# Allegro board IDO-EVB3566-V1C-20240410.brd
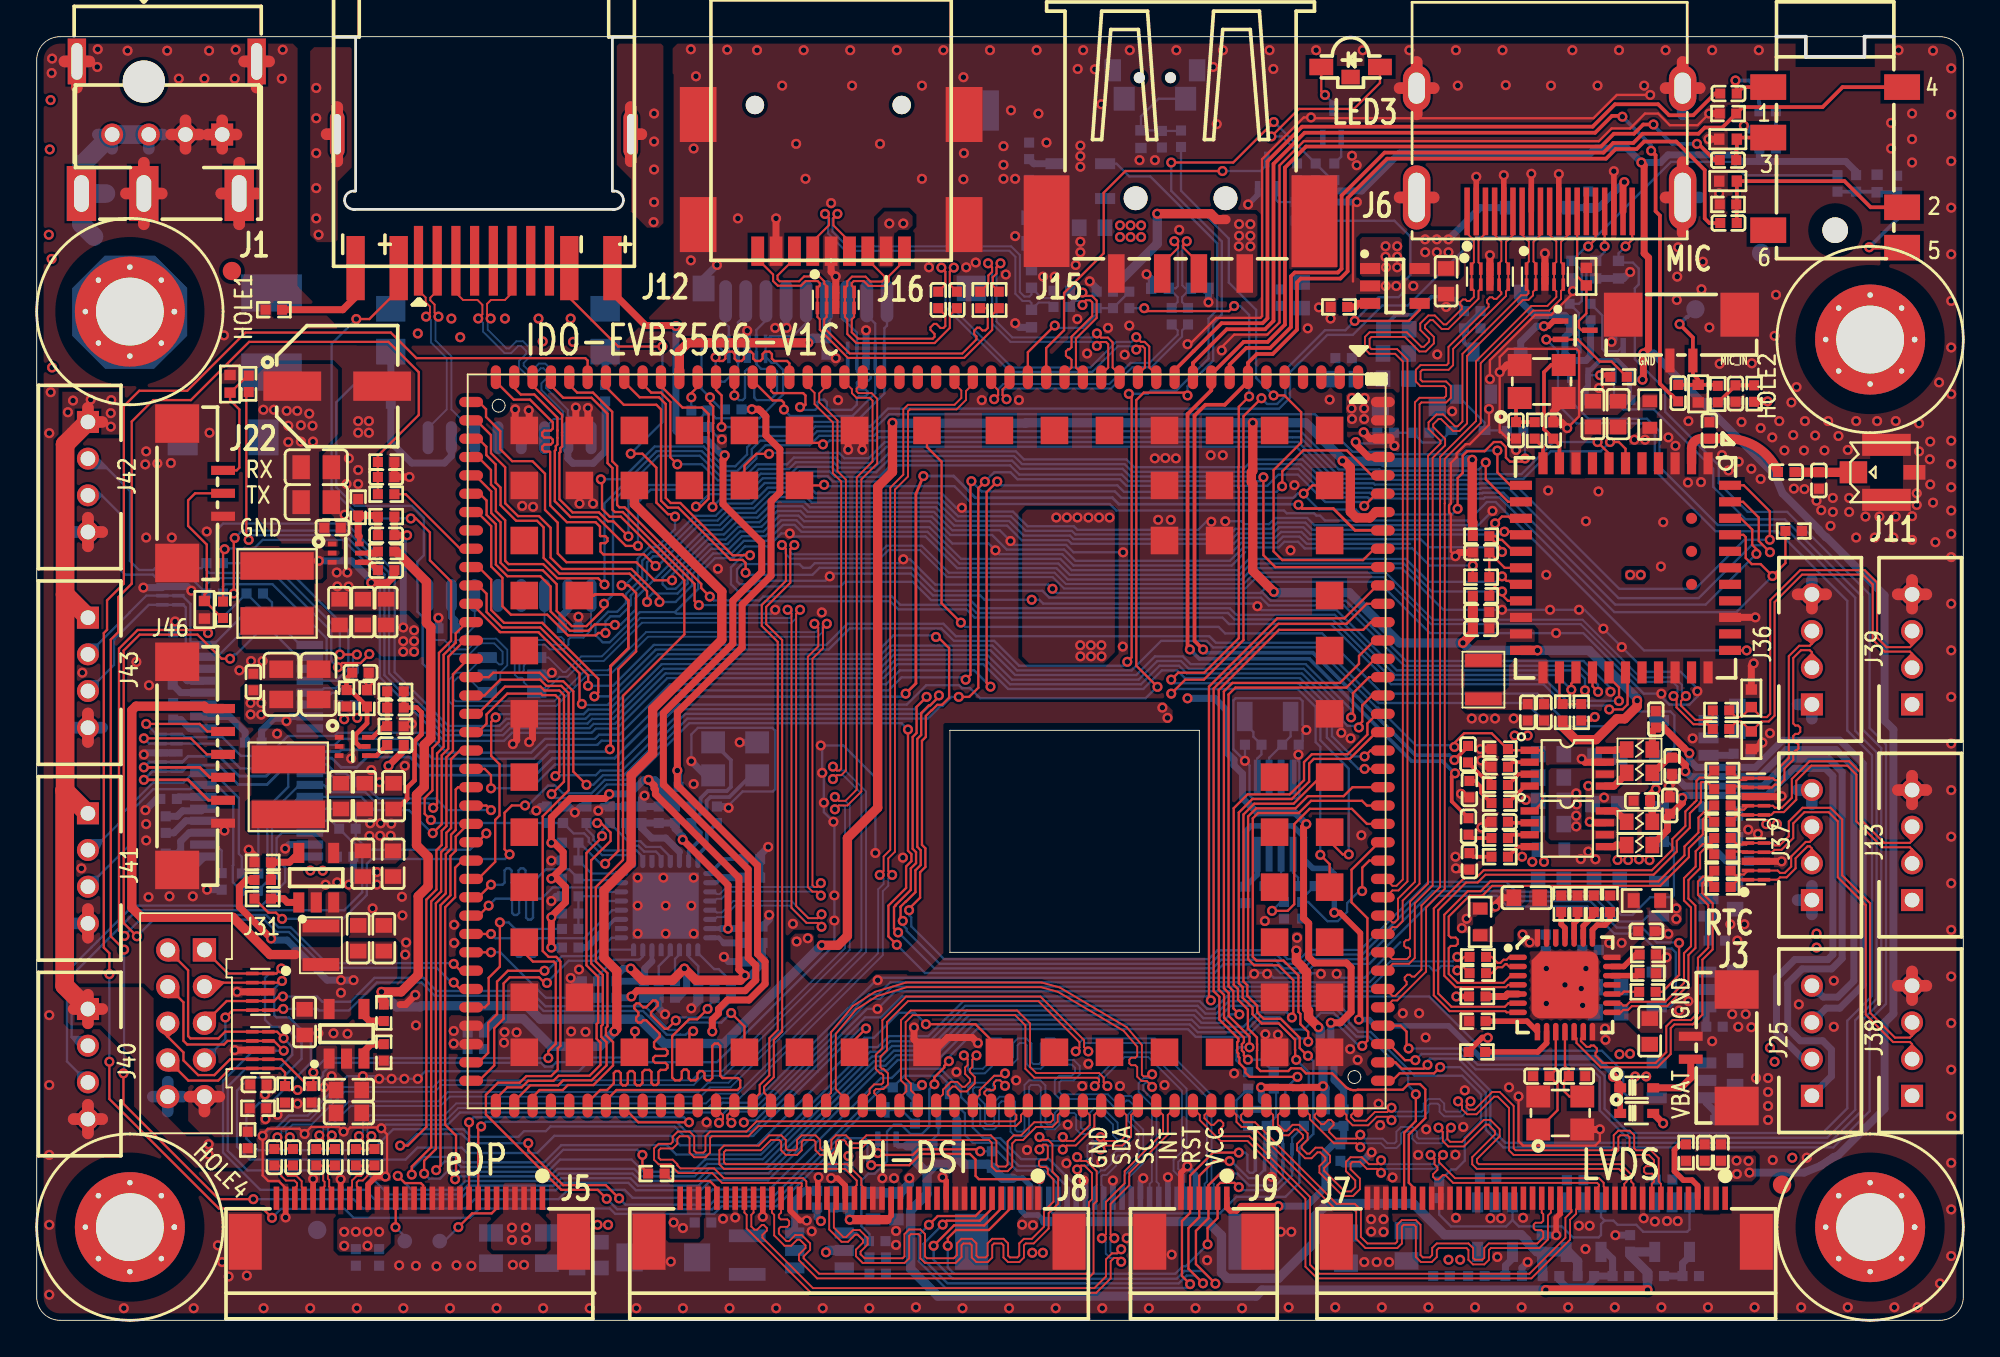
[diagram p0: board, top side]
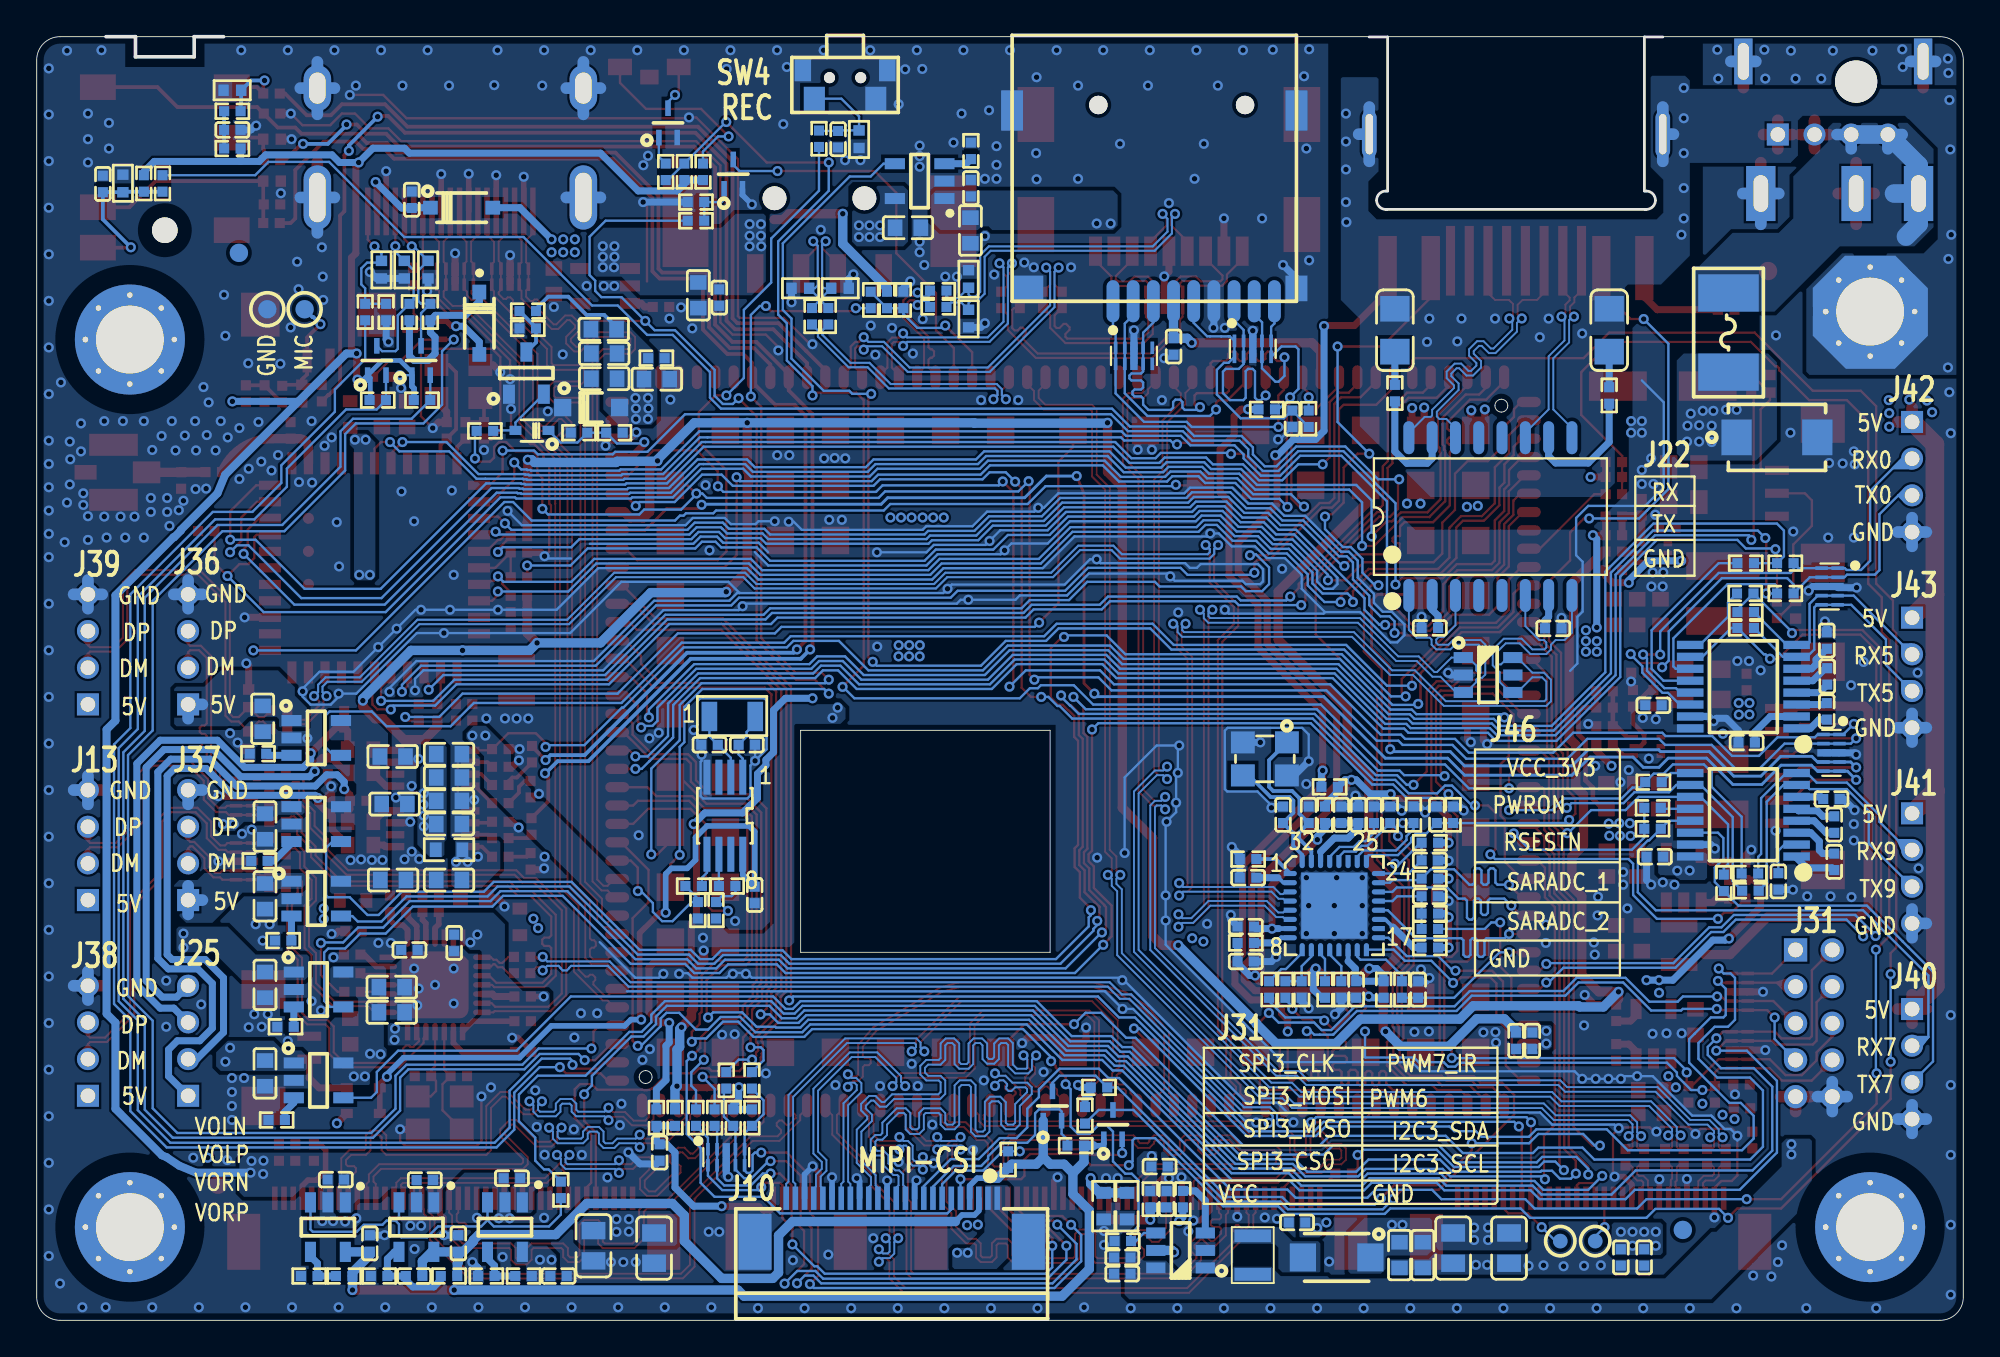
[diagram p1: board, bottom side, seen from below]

Outline 105.03 x 69.98 mm; copper layers: TOP, L2_GND, L3_S2, BOTTOM. Coordinates in mm from the lower left corner of the outline.
Outline path: 0,68.71 0,1.27 arc(0.37,0.37) 1.27,0 103.76,0 arc(104.66,0.37) 105.03,1.27 105.03,68.71 arc(104.66,69.61) 103.76,69.98 1.27,69.98 arc(0.37,69.61) 0,68.71

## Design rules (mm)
net group DIFFPAIR0: nets USB_HOST3_DM USB_HOST3_DP
net group DIFFPAIR1: nets USB_HOST2_DM USB_HOST2_DP
net group DIFFPAIR2: nets MIPI_CSI_RX_CLK0N MIPI_CSI_RX_CLK0P
net group DIFFPAIR3: nets MIPI_CSI_RX_D3N MIPI_CSI_RX_D3P
net group DIFFPAIR4: nets MIPI_CSI_RX_D2N MIPI_CSI_RX_D2P
net group DIFFPAIR5: nets MIPI_CSI_RX_D1N MIPI_CSI_RX_D1P
net group DIFFPAIR6: nets MIPI_CSI_RX_D0N MIPI_CSI_RX_D0P
net group DIFFPAIR7: nets MIPI_DSI_TX1_CLKN MIPI_DSI_TX1_CLKP
net group DIFFPAIR8: nets MIPI_DSI_TX1_D3N MIPI_DSI_TX1_D3P
net group DIFFPAIR9: nets MIPI_DSI_TX1_D2N MIPI_DSI_TX1_D2P
net group DIFFPAIR10: nets MIPI_DSI_TX1_D1N MIPI_DSI_TX1_D1P
net group DIFFPAIR11: nets MIPI_DSI_TX1_D0N MIPI_DSI_TX1_D0P
net group DIFFPAIR12: nets MIPI_DSI_TX0_CLKN/LVDS_TX0_CLKN MIPI_DSI_TX0_CLKP/LVDS_TX0_CLKP
net group DIFFPAIR13: nets MIPI_DSI_TX0_D3N/LVDS_TX0_D3N MIPI_DSI_TX0_D3P/LVDS_TX0_D3P
net group DIFFPAIR14: nets MIPI_DSI_TX0_D2N/LVDS_TX0_D2N MIPI_DSI_TX0_D2P/LVDS_TX0_D2P
net group DIFFPAIR15: nets MIPI_DSI_TX0_D1N/LVDS_TX0_D1N MIPI_DSI_TX0_D1P/LVDS_TX0_D1P
net group DIFFPAIR16: nets MIPI_DSI_TX0_D0N/LVDS_TX0_D0N MIPI_DSI_TX0_D0P/LVDS_TX0_D0P
net group DIFFPAIR17: nets HDMI_TX_CLKN HDMI_TX_CLKP
net group DIFFPAIR18: nets HDMI_TX_D0N HDMI_TX_D0P
net group DIFFPAIR19: nets HDMI_TX_D1N HDMI_TX_D1P
net group DIFFPAIR20: nets HDMI_TX_D2N HDMI_TX_D2P
net group DIFFPAIR21: nets USB3_HOST1SSRXN USB3_HOST1SSRXP
net group DIFFPAIR22: nets USB3_HOST1SSTXN USB3_HOST1SSTXP
net group DIFFPAIR23: nets USB_OTG0_DM_2 USB_OTG0_DP_2
net group DIFFPAIR48: nets RXN RXP
net group 90OHM: nets FE1.1_DM1 FE1.1_DM1_ FE1.1_DM2 FE1.1_DM2_ FE1.1_DM3 FE1.1_DM3_ FE1.1_DM4 FE1.1_DM4_ FE1.1_DP1 FE1.1_DP1_ FE1.1_DP2 FE1.1_DP2_ FE1.1_DP3 FE1.1_DP3_ FE1.1_DP4 FE1.1_DP4_ FE1_1_DM0 FE2_1_DP0 USB3_HOST1_DM USB3_HOST1_DM_2 USB3_HOST1_DP USB3_HOST1_DP_2 USB3_HOST1_SSRXN USB3_HOST1_SSRXP USB3_HOST1_SSTXN USB3_HOST1_SSTXP USB_HOST2_DM_ USB_HOST2_DP_ USB_OTG0_DM USB_OTG0_DP
net group 100OHM: nets EDP_TX_AUXN EDP_TX_AUXN_ EDP_TX_AUXP EDP_TX_AUXP_ EDP_TX_D0N EDP_TX_D0N_ EDP_TX_D0P EDP_TX_D0P_ EDP_TX_D1N EDP_TX_D1N_ EDP_TX_D1P EDP_TX_D1P_ RN RP TN TP TXN TXP

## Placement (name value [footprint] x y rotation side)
C1  100uF/25V  [CAPAE660X540]  16.38 50.93 0 top
C2  100nF  [C0402]  19.56 31.37 180 top
C3  100nF  [C0402]  19.05 40.89 180 top
C4  10uF  [C0805]  13.34 34.67 270 top
C5  10uF  [C0805]  15.37 34.67 270 top
C6  100pF  [C0402]  19.56 33.4 0 top
C7  22uF  [C0603]  17.88 28.57 270 top
C8  22uF  [C0603]  17.78 24.89 90 top
C9  100nF  [C0402]  11.81 34.8 270 top
C10  22uF  [C0603]  19.46 28.57 270 top
C11  10uF  [C0805]  15.24 44.6 180 top
C12  10uF  [C0805]  15.24 46.51 180 top
C13  100pF  [C0402]  19.05 42.8 0 top
C14  22uF  [C0603]  16.51 38.61 270 top
C15  22uF  [C0603]  17.78 38.61 270 top
C16  22uF  [C0603]  19.05 38.61 270 top
C17  100nF  [C0402]  16.13 43.21 180 top
C18  22uF  [C0603]  16.59 28.57 270 top
C20  22uF  [C0603]  19.43 24.89 90 top
C21  22uF  [C0603]  18.92 20.83 270 top
C22  22uF  [C0603]  14.61 16.26 90 top
C23  22uF  [C0603]  17.53 20.83 270 top
C24  22uF  [C0603]  17.02 11.3 180 top
C25  22uF  [C0603]  17.02 12.55 180 top
C26  1uF  [C0402]  23.5 15.24 90 bottom
C27  22uF  [C0603]  74.09 51.33 180 bottom
C28  22uF  [C0603]  71.22 51.31 0 bottom
C29  1uF  [C0402]  24.38 15.24 90 bottom
C30  18pF  [C0402]  66.32 31.38 0 bottom
C31  18pF  [C0402]  68.35 31.38 180 bottom
C32  1uF  [C0402]  65.89 23.19 90 bottom
C33  100nF  [C0402]  61.34 64.39 90 bottom
C34  100nF  [C0402]  18.41 8.89 90 top
C35  100nF  [C0402]  17.4 8.89 90 top
C36  100nF  [C0402]  12.95 8.89 90 top
C37  100nF  [C0402]  13.97 8.89 90 top
C38  100nF  [C0402]  15.24 8.89 90 top
C39  100nF  [C0402]  16.26 8.89 90 top
C40  10uF  [C0402]  17.4 3.43 90 bottom
C41  10uF  [C0402]  18.67 3.43 90 bottom
C42  10uF  [C0805]  27.81 3.94 90 bottom
C43  10uF  [C0805]  24.77 3.94 90 bottom
C47  1uF  [C0402]  84.58 61.09 270 bottom
C48  10uF  [C0402]  90.93 9.14 270 top
C49  10uF  [C0402]  91.82 9.14 270 top
C50  10uF  [C0805]  74.68 4.06 90 bottom
C51  10uF  [C0805]  71.37 3.94 90 bottom
C53  1uF  [C0402]  43.43 6.6 270 bottom
C54  10uF  [C0402]  43.81 8.38 0 bottom
C55  10uF  [C0402]  36.32 5.33 180 bottom
C57  100nF  [C0402]  45.85 2.54 180 bottom
C58  1uF  [C0603]  29.46 3.56 90 bottom
C59  4.7uF  [C0402]  45.85 3.43 180 bottom
C60  1uF  [C0603]  30.73 3.56 90 bottom
C61  1uF  [C0402]  71.07 9.14 270 bottom
C62  NC/6.8pF  [C0402]  19.05 45.97 180 top
C63  10uF  [C0402]  79.12 7.75 180 bottom
C64  10uF  [C0402]  76.58 2.41 0 bottom
C67  10uF  [C0402]  88.72 7.67 180 bottom
C68  10uF  [C0402]  86.87 4.19 270 bottom
C72  10uF  [C0402]  83.87 7.65 180 bottom
C73  10uF  [C0402]  82.04 4.19 270 bottom
C76  NC/6.8pF  [C0402]  78.74 41.86 0 top
C77  10pF  [C0402]  95.38 46.24 180 top
C78  18pF  [C0402]  82.68 48.51 90 top
C79  NC/10pF  [C0402]  91.19 48.51 270 top
C80  NC/10pF  [C0402]  97.16 45.78 90 top
C81  18pF  [C0402]  80.64 48.51 90 top
C82  22uF  [C0603]  84.84 49.4 270 top
C83  22uF  [C0603]  86.21 49.4 270 top
C85  1uF  [C0402]  78.74 37.72 180 top
C86  100nF  [C0402]  78.74 38.61 180 top
C90  4.7uF  [C0402]  81.28 33.15 90 top
C91  100nF  [C0402]  82.17 33.15 90 top
C123  10uF  [C0603]  76.83 56.64 270 top
C124  10uF  [C0603]  57.53 59.56 180 bottom
C125  100nF  [C0402]  50.16 55.63 270 top
C126  100nF  [C0402]  49.15 55.63 270 top
C129  10uF  [C0603]  92.58 18.29 90 bottom
C131  10uF  [C0603]  85.67 18.16 0 bottom
C145  10uF  [C0603]  92.71 32.79 90 bottom
C146  10uF  [C0603]  85.62 30.73 0 bottom
C150  10uF  [C0603]  92.58 23.11 90 bottom
C151  10uF  [C0603]  85.6 24 0 bottom
C153  10uF  [C0603]  92.58 13.46 90 bottom
C154  10uF  [C0603]  85.67 16.79 0 bottom
C155  NC/6.8pF  [C0402]  36.58 49.15 90 bottom
C156  10uF  [C0402]  43.05 53.09 90 bottom
C157  10uF  [C0402]  92.23 59.82 180 top
C158  10uF  [C0402]  92.61 50.52 90 top
C159  NC/100nF  [C0402]  101.42 61.95 270 bottom
C160  10uF  [C0402]  92.2 63.25 180 top
C161  10uF  [C0402]  94.36 64.9 0 bottom
C175  1uF  [C0402]  16.81 25.27 180 bottom
C176  100nF  [C0402]  7.04 24.99 270 bottom
C177  100nF  [C0402]  7.04 27.03 270 bottom
C178  100nF  [C0402]  10.08 23.93 90 bottom
C179  100nF  [C0402]  7.19 28.42 0 bottom
C180  1uF  [C0402]  16.89 33.53 180 bottom
C181  100nF  [C0402]  7.44 33.2 270 bottom
C182  100nF  [C0402]  7.42 35.1 270 bottom
C183  100nF  [C0402]  11.81 31.5 180 bottom
C184  100nF  [C0402]  7.44 37.06 270 bottom
C185  10uF  [C0402]  12.09 12.85 180 top
C186  1uF  [C0402]  79.76 30.18 0 top
C187  100nF  [C0402]  78.03 30.86 270 top
C188  100nF  [C0402]  78.11 28.96 90 top
C192  1nF  [C0402]  88.27 32.77 90 top
C193  1nF  [C0402]  89.15 30.23 270 top
C194  1uF  [C0402]  79.76 27.18 0 top
C195  100nF  [C0402]  78.05 26.92 270 top
C196  100nF  [C0402]  78.11 25.02 90 top
C197  1nF  [C0402]  87.5 28.32 180 top
C198  1nF  [C0402]  89.03 28.07 90 top
C202  18pF  [C0402]  83.97 13.31 180 top
C203  18pF  [C0402]  82.02 13.31 0 top
C298  100nF  [C0402]  87.76 21.21 180 top
C322  100nF  [C0402]  84.71 20.19 0 bottom
C324  100nF  [C0402]  82.27 20.57 90 bottom
C333  22uF  [C0603]  81.23 23.04 0 top
C334  22uF  [C0603]  87.93 15.75 270 top
C341  22uF  [C0603]  68.96 55.88 90 bottom
C343  100nF  [C0402]  67.82 55.75 90 bottom
C344  22uF  [C0603]  54.13 59.41 90 bottom
C346  100nF  [C0402]  54.1 61.72 270 bottom
C357  10uF  [C0603]  85.52 28.14 0 bottom
C358  10uF  [C0603]  92.58 26.92 90 bottom
C359  22uF  [C0603]  82.55 29.59 0 bottom
C360  22uF  [C0603]  82.55 28.32 0 bottom
C361  22uF  [C0603]  82.55 27.05 0 bottom
C362  22uF  [C0603]  82.55 30.86 0 bottom
C363  22uF  [C0603]  82.55 24 180 bottom
C365  100nF  [C0402]  92.23 66.88 180 top
C366  100nF  [C0402]  89.48 50.55 270 top
C369  22uF  [C0603]  74.12 54.03 180 bottom
C370  22uF  [C0603]  74.09 52.7 180 bottom
C371  100nF  [C0402]  22.35 37.72 0 bottom
C372  100nF  [C0402]  29.08 37.74 180 bottom
C380  10uF  [C0402]  39.12 21.46 180 bottom
C381  10uF  [C0402]  33.1 18.03 90 bottom
C383  NC/6.8pF  [C0402]  29.72 18.03 270 bottom
C384  100nF  [C0402]  29.08 23.11 0 bottom
C385  100nF  [C0402]  38.99 24.13 180 bottom
C386  18pF  [C0402]  37.08 27.56 90 bottom
C387  18pF  [C0402]  35.69 27.56 270 bottom
C388  100nF  [C0402]  32.13 27.56 270 bottom
C389  100nF  [C0402]  33.91 27.56 270 bottom
C390  100nF  [C0402]  32.97 27.56 270 bottom
C391  100nF  [C0402]  39.12 19.56 0 bottom
C392  100pF  [C0402]  29.08 25.07 0 bottom
C393  100pF  [C0402]  28.7 27.56 90 bottom
C394  NC/10pF  [C0402]  84.45 2.41 180 bottom
C395  1nF  [C1206]  19.3 53.98 270 bottom
C396  1nF  [C1206]  30.99 53.98 270 bottom
C397  100nF  [C0402]  17.65 35.31 180 top
D1  SMBJ16A  [SMB_DO-214AA]  10.16 48.13 180 bottom
D2  SMF6.0CA  [SOD-123F]  74.8 49.76 0 bottom
D3  LRB520S-30T1G  [SOD523]  87.22 11.28 0 top
D4  LRB520S-30T1G  [SOD523]  87.22 12.67 0 top
D5  PE0402N12G01B  [V0402]  60.2 64.39 270 bottom
D6  SE05NRC14GA  [DFN2510-10L]  79.22 56.9 0 top
D7  SE05NRC14GA  [DFN2510-10L]  82.22 56.9 0 top
D8  PE0402N12G01B  [V0402]  86.23 57.28 270 bottom
D9  PE0402N12G01B  [V0402]  84.48 56.9 90 top
D10  PE0402N12G01B  [V0402]  83.69 57.28 270 bottom
D11  PE0402N12G01B  [V0402]  84.99 57.28 270 bottom
D12  B5819W-G  [SOD123]  80.9 54.36 270 bottom
D13  B5819W-G  [SOD123]  81.86 60.66 180 bottom
D18  SE05NRC14GA  [DFN2510-10L]  67.44 8.89 180 bottom
D23  SM340AF  [SMAF]  34.16 3.43 180 bottom
D26  PE0402N12G01B  [V0402]  63.4 56.26 180 bottom
D27  PE0402N12G01B  [V0402]  61.24 56.26 180 bottom
D28  PE0402N12G01B  [V0402]  54.23 56.77 270 bottom
D29  PE0402N12G01B  [V0402]  54.23 54.61 270 bottom
D30  SE05NRC14GA  [DFN2510-10L]  43.56 55.63 0 top
D31  SE05NRC14GA  [DFN2510-10L]  93.73 28.55 90 top
D32  SE05NRC14GA  [DFN2510-10L]  93.73 25.02 90 top
D33  SE05NRC14GA  [DFN2510-10L]  45.21 52.58 180 bottom
D34  SE05NRC14GA  [DFN2510-10L]  38.73 52.96 180 bottom
D35  PE0402N12G01B  [V0402]  10.54 51.05 270 top
D36  PE0402N12G01B  [V0402]  9.14 38.73 90 top
D37  PE0402N12G01B  [V0402]  92.2 62.1 180 top
D38  PE0402N12G01B  [V0402]  100.33 61.98 90 bottom
D39  PE0402N12G01B  [V0402]  92.2 64.39 180 top
D40  PE0402N12G01B  [V0402]  94.36 67.06 0 bottom
D41  PE0402N12G01B  [V0402]  90.58 50.52 270 top
D43  SE05NRC14GA  [DFN2510-10L]  7.29 40.01 270 bottom
D44  SE05NRC14GA  [DFN2510-10L]  12.19 17.91 270 top
D45  SE05NRC14GA  [DFN2510-10L]  12.19 14.73 270 top
D46  PE0402N12G01B  [V0402]  93.47 31.62 270 top
D47  PE0402N12G01B  [V0402]  93.47 33.91 90 top
D81  SRV05-4  [SOT23-6]  25.91 35.18 180 bottom
D82  SE05NRC14GA  [DFN2510-10L]  7.19 30.94 270 bottom
D86  LRB520S-30T1G  [SOD523]  78.03 48.51 0 bottom
F1  FUSE_16V/2.6A  [SMD1812]  12.8 53.85 270 bottom
HOLE1  -  [MTG370_600_VIA]  5.08 54.99 0 top
HOLE2  -  [MTG370_600_VIA]  99.95 53.47 0 top
HOLE3  -  [MTG370_600_VIA]  99.95 5.08 0 top
HOLE4  -  [MTG370_600_VIA]  5.08 5.08 0 top
J1  DC-044A-2_5  [DC-044A-2_0-DIP]  5.84 71.63 270 top
J2  PH2.0-4A  [PH200-4A]  7.11 64.64 0 top
J3  MX1.25T-S-2A  [MX125T-S-2A]  90.17 14.86 90 top
J5  FPC05-FDW-30P  [FPC05-30P]  20.32 5.08 0 top
J6  -  [HDMI-TYPEA_SMD]  77.98 60.45 0 top
J7  FPC05-FDW-40P  [FPC05-40P]  82.3 5.08 0 top
J8  FPC05-FDW-40P  [FPC05-40P]  44.83 5.08 0 top
J9  FPC05-UD-6P  [FPC05-6P]  63.63 5.08 0 top
J10  FPC05-PUW-24P  [FPC05-24P]  58.42 5.08 180 bottom
J11  IPEX  [IPEX-001E]  100.84 46.23 180 top
J12  HR6042AS-1188N15B-21-1R  [RJ45_SMD_1188N]  24.38 68.96 180 top
J13  PH2.0-4A  [PH200-4A]  102.23 25.91 270 top
J15  USB-4AF-SMD  [USB_4A_SMD]  62.36 56.77 180 top
J16  USB-9AF-SMD  [JLX-USB-G36]  43.31 57.78 180 top
J21  SD  [TF-01A]  46.35 55.75 0 bottom
J22  MX1.25T-S-3A  [MX125T-S-3A]  10.16 45.09 270 top
J25  PH2.0-4A  [PH200-4A]  96.77 15.24 270 top
J31  PHD2.0-2X5A  [PHD200-2X5A]  9.14 20.19 90 top
J34  PJ-316-6A  [PJ-316A-6A]  98.04 69.98 90 top
J36  PH2.0-4A  [PH200-4A]  96.77 36.58 270 top
J37  PH2.0-4A  [PH200-4A]  96.77 25.91 270 top
J38  PH2.0-4A  [PH200-4A]  102.23 15.24 270 top
J39  PH2.0-4A  [PH200-4A]  102.23 36.58 270 top
J40  PH2.0-4A  [PH200-4A]  2.79 13.97 90 top
J41  PH2.0-4A  [PH200-4A]  2.79 24.64 90 top
J42  PH2.0-4A  [PH200-4A]  2.79 45.97 90 top
J43  PH2.0-4A  [PH200-4A]  2.79 35.31 90 top
J45  MX1.25T-S-2A  [MX125T-S-2A]  89.66 52.32 180 top
J46  MX1.25T-S-6A  [MX125T-S-6A]  10.16 30.23 270 top
L1  2.2uH/4.3A  [IND_404020]  13.72 29.08 270 top
L2  2.2uH/4.3A  [IND_404020]  13.11 39.62 270 top
L3  1uH/3A  [IND_252012]  15.49 20.45 270 top
L5  4.7uH/1.25A  [IND_252012]  38.73 3.56 90 bottom
L6  4.7uH/1.25A  [IND_252012]  78.87 34.92 270 top
L21  UPZ1608E101-3R0TF  [L0603]  87.38 31.11 0 top
L22  UPZ1608E101-3R0TF  [L0603]  87.38 29.84 0 top
L23  UPZ1608E101-3R0TF  [L0603]  87.38 27.18 0 top
L24  UPZ1608E101-3R0TF  [L0603]  87.38 25.91 0 top
LED3  Yellow LED  [LED-SMD_3_2X1_5X1_0]  71.63 68.33 180 top
M1  -  [SOM3566-239P]  73.53 51.56 180 top
MARK1  NC/FID10X20  [FID10X20]  10.64 57.2 0 top
MARK2  NC/FID10X20  [FID10X20]  95.15 7.39 0 top
MARK3  NC/FID10X20  [FID10X20]  15.29 4.93 180 bottom
MARK4  NC/FID10X20  [FID10X20]  94.01 58.19 180 bottom
Q1  MMFTN3019E  [SOT523]  83.87 53.98 0 top
Q2  MMFTN3019E  [SOT523]  84.07 52.32 90 bottom
Q3  MMFTN3019E  [SOT523]  86.49 52.32 90 bottom
Q5  MMFTN3019E  [SOT523]  67.06 62.48 90 bottom
Q8  MMFTN3019E  [SOT523]  46.35 10.67 90 bottom
Q9  MMFTN3019E  [SOT523]  49.66 11.68 90 bottom
Q10  MMFTN3019E  [SOT523]  70.61 65.28 90 bottom
R3  100K  [R0402]  19.56 34.29 0 top
R4  107K  [R0402]  19.05 43.81 0 top
R5  100K  [R0402]  16.89 33.91 90 top
R6  10K  [R0402]  19.05 41.91 180 top
R7  47K  [R0402]  18.01 33.91 270 top
R8  20K  [R0402]  19.56 32.38 180 top
R9  20K  [R0402]  17.53 44.32 270 top
R10  45.3K  [R0402]  12.32 24 180 top
R11  10K  [R0402]  12.32 22.99 0 top
R12  10K  [R0402]  12.32 24.97 0 top
R14  10K  [R0402]  18.92 16.76 90 top
R16  100R  [R0402]  19.05 45.03 0 top
R17  120R  [R0402]  19.05 46.79 180 top
R18  100K  [R0402]  73.53 48.39 180 bottom
R19  4.7K  [R0402]  68.71 62.61 90 bottom
R20  47K  [R0402]  75.46 48.39 180 bottom
R21  2.2K  [R0402]  68.99 22.35 270 bottom
R22  2.2K  [R0402]  68 22.35 270 bottom
R23  22R  [R0402]  67.39 23.67 180 bottom
R24  22R  [R0402]  69.22 23.67 0 bottom
R25  100R  [R0402]  62.38 64.41 90 bottom
R28  4.7K  [R0402]  87.12 54.97 90 bottom
R29  20K  [R0402]  86.23 51.44 180 top
R30  100K  [R0402]  85.98 54.97 90 bottom
R31  10K  [R0402]  84.02 50.16 180 bottom
R32  1.8K  [R0402]  83.57 54.97 90 bottom
R33  10K  [R0402]  86.44 50.16 180 bottom
R34  1.8K  [R0402]  84.71 54.97 90 bottom
R38  0R  [R0402]  44.32 6.6 270 bottom
R39  22R  [R0402]  66.04 13.08 270 bottom
R40  2.2K  [R0402]  66.04 11.05 90 bottom
R41  22R  [R0402]  67.44 13.08 270 bottom
R42  2.2K  [R0402]  67.06 11.05 90 bottom
R43  22R  [R0402]  69.09 11.05 270 bottom
R44  22R  [R0402]  68.07 11.05 270 bottom
R46  0R  [R0402]  70.23 11.05 270 bottom
R47  NC/0R  [R0402]  71.25 11.05 270 bottom
R48  100K  [R0402]  42.55 6.6 90 bottom
R49  100K  [R0402]  45.82 4.32 180 bottom
R50  3.9R  [R0603]  46.86 6.22 90 bottom
R51  3.9R  [R0603]  45.59 6.22 90 bottom
R56  49.9K  [R0402]  78.49 2.41 180 bottom
R57  20K  [R0402]  80.52 2.41 180 bottom
R59  24.9K  [R0402]  88.27 2.41 180 bottom
R60  20K  [R0402]  90.17 2.41 180 bottom
R63  17.4K  [R0402]  82.55 2.41 180 bottom
R64  20K  [R0402]  86.36 2.41 180 bottom
R65  NC/10K  [R0402]  78.74 39.5 0 top
R66  NC/10K  [R0402]  78.74 42.75 0 top
R67  22R  [R0402]  78.74 40.51 0 top
R68  0R  [R0402]  81.66 48.51 270 top
R69  NC/10K  [R0402]  95.78 43.03 0 top
R71  0R  [R0603]  87.93 49.38 90 top
R73  10K  [R0402]  83.19 33.15 90 top
R74  0R  [R0402]  84.2 33.15 90 top
R116  2.2R  [R0402]  62.76 54.74 90 bottom
R117  1K  [R0402]  69.09 59.94 0 bottom
R118  2.2R  [R0402]  61.87 54.74 90 bottom
R119  10K  [R0402]  69.09 60.96 0 bottom
R120  0R  [R0402]  59.56 55.63 90 bottom
R121  10K  [R0402]  58.67 55.63 90 bottom
R122  4.7K  [R0402]  70.99 55.24 0 top
R123  20K  [R0402]  57.78 55.63 270 bottom
R124  2.2R  [R0402]  55.88 56.13 180 bottom
R126  2.2R  [R0402]  55.88 55.24 180 bottom
R127  0R  [R0402]  52.45 55.63 270 top
R128  0R  [R0402]  51.44 55.63 270 top
R129  4.7K  [R0402]  54.1 63.75 270 bottom
R131  2.2R  [R0402]  91.9 27.18 0 top
R132  2.2R  [R0402]  91.9 28.07 0 top
R136  4.7K  [R0402]  91.47 16 0 bottom
R146  2.2R  [R0402]  91.9 28.96 0 top
R148  4.7K  [R0402]  92.96 30.89 0 bottom
R149  2.2R  [R0402]  91.9 29.97 0 top
R151  2.2R  [R0402]  91.9 23.62 0 top
R153  4.7K  [R0402]  91.59 20.7 0 bottom
R154  2.2R  [R0402]  91.9 24.51 0 top
R156  2.2R  [R0402]  91.9 25.4 0 top
R158  4.7K  [R0402]  91.95 10.92 0 bottom
R159  2.2R  [R0402]  91.9 26.29 0 top
R160  22R  [R0402]  35.69 49.15 270 bottom
R161  100R  [R0402]  11.56 51.05 90 top
R162  100R  [R0402]  10.16 38.73 270 top
R163  1K  [R0402]  93.62 50.52 90 top
R164  100K  [R0402]  99.19 61.98 90 bottom
R165  0R  [R0402]  92.2 65.79 0 top
R166  1K  [R0402]  98.17 61.98 270 bottom
R167  1K  [R0402]  91.64 50.5 270 top
R169  1K  [R0402]  94.36 65.91 0 bottom
R170  1K  [R0402]  94.36 63.88 180 bottom
R173  NC/22R  [R0402]  13.06 23.85 270 bottom
R174  NC/22R  [R0402]  16.94 26.8 180 bottom
R175  NC/22R  [R0402]  11.61 23.42 180 bottom
R176  NC/22R  [R0402]  11.63 24.36 180 bottom
R177  22R  [R0402]  16.89 29.34 180 bottom
R178  22R  [R0402]  16.94 27.94 180 bottom
R183  22R  [R0402]  9.7 39.62 180 bottom
R184  22R  [R0402]  9.7 41.27 180 bottom
R185  22R  [R0402]  11.86 37.74 180 bottom
R186  22R  [R0402]  11.86 38.61 180 bottom
R189  NC/22R  [R0402]  11.86 41.27 0 bottom
R190  NC/22R  [R0402]  11.89 39.62 0 bottom
R193  2.2K  [R0402]  14.99 12.32 270 top
R194  2.2K  [R0402]  13.54 12.32 270 top
R195  NC/0R  [R0402]  11.51 9.83 90 top
R196  0R  [R0402]  12.06 11.56 180 top
R197  20K  [R0402]  79.76 29.18 0 top
R198  20K  [R0402]  79.76 28.19 0 top
R199  100K  [R0402]  79.76 31.14 0 top
R200  20K  [R0402]  79.76 26.29 0 top
R201  20K  [R0402]  79.76 25.27 0 top
R231  2.2K  [R0402]  78.26 54.08 180 bottom
R232  1K  [R0402]  78.26 55.02 180 bottom
R292  10K  [R0402]  87.83 18.92 0 top
R293  NC/100K  [R0402]  84.89 22.71 90 top
R294  NC/100K  [R0402]  85.78 22.71 90 top
R295  NC/680R  [R0402]  78.54 16.31 0 top
R296  NC/0R  [R0402]  78.54 17.65 0 top
R297  NC/0R  [R0402]  78.51 14.63 0 top
R298  0R  [R0402]  78.56 18.92 0 top
R299  0R  [R0402]  78.56 19.81 0 top
R300  10K  [R0402]  84 22.71 90 top
R301  10K  [R0402]  83.11 22.71 90 top
R302  10K  [R0402]  87.83 19.94 0 top
R325  2.2R  [R0402]  91.82 32.23 0 top
R326  2.2R  [R0402]  91.82 33.25 0 top
R327  4.7K  [R0402]  92.89 25.04 0 bottom
R331  10K  [R0402]  92.2 60.83 180 top
R333  1.8K  [R0402]  47.12 12.7 180 bottom
R334  1.8K  [R0402]  47.88 11.18 270 bottom
R338  0R  [R0603]  82.55 25.65 0 bottom
R342  22R  [R0402]  33.78 8 0 top
R343  22R  [R0402]  87.81 17.91 0 top
R344  10K  [R0402]  37.97 49.66 180 bottom
R345  0R  [R0603]  87.78 22.89 180 top
R346  0R  [R0603]  78.69 21.72 270 top
R415  10K  [R0402]  69.72 62.61 90 bottom
R500  10K  [R0402]  71.25 52.45 180 bottom
R1201  22R  [R0402]  29.08 21.34 0 bottom
R1202  NC/4.7K  [R0402]  29.08 22.17 180 bottom
R1203  10K  [R0402]  29.08 20.32 180 bottom
R1204  4.7K  [R0402]  29.08 24.08 0 bottom
R1205  22R  [R0402]  36.96 18.03 270 bottom
R1206  22R  [R0402]  37.85 18.03 270 bottom
R1207  2.49K  [R0402]  38.99 25.15 0 bottom
R1209  4.7K  [R0402]  29.97 27.56 270 bottom
R1210  510R  [R0402]  12.93 55.09 0 top
R1211  510R  [R0402]  31.6 18.03 270 bottom
R1212  4.7K  [R0402]  31.24 27.56 90 bottom
R1213  4.7K  [R0402]  39.12 20.57 0 bottom
R1214  4.7K  [R0402]  33.91 18.03 270 bottom
R1215  4.7K  [R0402]  36.07 18.03 270 bottom
R1217  4.7K  [R0402]  27.81 27.56 270 bottom
R1218  4.7K  [R0402]  29.08 26.04 0 bottom
R1219  4.7K  [R0402]  34.8 18.03 270 bottom
R1220  4.7K  [R0402]  18.92 14.61 90 top
R1221  22R  [R0402]  76.45 7.11 270 bottom
R1222  2.2K  [R0402]  52.07 8.76 270 bottom
R1223  2.2K  [R0402]  48.39 9.53 180 bottom
R1224  22R  [R0402]  30.61 18.03 90 bottom
R1225  0R  [R0402]  34.8 27.56 270 bottom
R1226  0R  [R0402]  34.54 29.08 180 bottom
R1227  4.7K  [R0402]  70.74 62.61 90 bottom
R1228  75R  [R0402]  30.99 50.55 90 bottom
R1229  75R  [R0402]  19.3 50.42 90 bottom
R1230  0R  [R0402]  89.92 9.14 90 top
R1231  0R  [R0402]  80.59 48.49 0 bottom
SW4  T-switch  [PB-SIDE-S-3_5X4_5]  60.96 67.94 0 bottom
TP1  -  [TP80]  20.07 4.32 180 bottom
TP2  -  [TP80]  21.97 4.32 180 bottom
TP3  -  [TP100]  90.42 55.12 180 bottom
TP4  -  [TP100]  92.46 55.12 180 bottom
U1  ETA1654FSG  [SOT563]  16.13 32.38 0 top
U2  ETA1654FSG  [SOT563]  15.75 42.93 0 top
U3  ETA3417S2F  [SOT23-5]  15.24 24.13 90 top
U4  ETA6280S2F  [SOT23-5]  16.89 15.62 90 top
U5  HYM8563S  [TSSOP-8]  67.51 27.51 270 bottom
U6  SY7201ABC  [SOT23-6]  42.67 3.81 0 bottom
U7  ETA5050V0S2F  [SOT23-5]  79.5 5.08 270 bottom
U8  ETA5050V0S2F  [SOT23-5]  89.15 5.08 270 bottom
U9  ETA5050V0S2F  [SOT23-5]  84.33 5.08 270 bottom
U10  AP6256  MODULE  [WIFI_44P_12X12]  86.61 41.02 270 top
U11  YT8512C  [QFN-32_5X5X05P]  34.29 22.61 180 bottom
U13  ETA6280S2F  [SOT23-5]  74.04 56.39 0 top
U14  ETA6280S2F  [SOT23-5]  56.9 62.1 0 bottom
U15  ETA6280S2F  [SOT23-5]  89.66 18.03 180 bottom
U17  ETA6280S2F  [SOT23-5]  89.79 31.75 180 bottom
U18  ETA6280S2F  [SOT23-5]  89.79 22.99 180 bottom
U19  ETA6280S2F  [SOT23-5]  89.66 13.08 180 bottom
U21  SP3232EEY-L/TR  [TSSOP-16]  11.99 27.56 0 bottom
U22  NC/SP3232EEY-L/TR  [TSSOP-16]  11.99 34.54 0 bottom
U23  H81621S  [SOP16-P127-710X1270]  25.78 43.81 90 bottom
U24  NS4150B  [MSOP-8]  83.44 30.1 0 top
U25  NS4150B  [MSOP-8]  83.44 26.8 0 top
U26  CH334H  [QFN-28_5X5X05P]  83.31 18.29 0 top
U27  ETA6280S2F  [SOT23-5]  89.79 27.05 180 bottom
U28  NC/SGM803-SXN3L/TR  [SOT23]  78.33 51.64 90 bottom
XT1  32.768KHz  [XTAL_32X15_2P]  67.11 32.92 180 bottom
XT2  37.4MHz  [XTAL_32X25_4P]  82.04 51.18 90 top
XT4  25MHz  [XTAL_32X25_4P]  38.07 30.61 270 bottom
XT5  12MHz  [XTAL_32X25_4P]  83.06 11.3 90 top

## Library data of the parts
C1 = C-G-SMD
C2 C3 C6 C9 C13 C17 C26 C29-C41 C47-C49 C53-C55 C57 C59 C61-C64 C67 C68 C72 C73 C76-C81 C85 C86 C90 C91 C125 C126 C155-C161 C175-C188 C192-C198 C202 C203 C298 C322 C324 C343 C346 C365 C366 C371 C372 C380 C381 C383-C394 C397 = C-0402
C4 C5 C11 C12 C42 C43 C50 C51 = C-0805
C7 C8 C10 C14-C16 C18 C20-C25 C27 C28 C58 C60 C82 C83 C123 C124 C129 C131 C145 C146 C150 C151 C153 C154 C333 C334 C341 C344 C357-C363 C369 C370 = C-0603
C395 C396 = C-1206
D1 D3 D4 D12 D13 D23 D86 = DI-XI-S
D2 = DI-TVS-D
D5 D8-D11 D26-D29 D35-D41 D46 D47 = DI-ESD
D6 D7 D18 D30-D34 D43-D45 D82 = DI-ESD-SE05NRC14GA
D81 = DI-TVS-SRV05-4
F1 = FUSE-SMD1812: User Part Number: HAMP; Tolerance: #TOL
HOLE1-HOLE4 = MH-NOE: Tolerance: RichardLC; User Part Number: pn
J1 = J-DC-044A-2_5
J2 = J-H-4P
J3 J45 = J-A-2P
J5 = J-FPC-30P
J6 = J-HDMI-19P
J7 J8 = J-FPC-40P
J9 = J-FPC-6P
J10 = J-FPC-24P
J11 = RF-IPEX-20279
J12 = J-RJ45-MJ88B-B011-RVL11-P_2
J13 J36-J43 = J-H-4P_0
J15 = J-USB-4AF_1
J16 = J-USB-9AF-W_0
J21 = J-TF-01A
J22 = J-A-3P
J25 = J-H-4P_9
J31 = J-H-2X5P
J34 = J-PJ-316A-6A_0
J46 = J-A-6P
L1-L3 L5 L6 = L-IND
L21-L24 = FB-0603
LED3 = D-LED-CT
M1 = SOM3566-239P_3
MARK1-MARK4 = MARK-FID10X20_0
Q1-Q3 Q5 Q8-Q10 = N-MOS-Q
R3-R12 R14 R16-R25 R28-R34 R38-R44 R46-R49 R56 R57 R59 R60 R63-R69 R73 R74 R116-R124 R126-R129 R131 R132 R136 R146 R148 R149 R151 R153 R154 R156 R158-R167 R169 R170 R173-R178 R183-R186 R189 R190 R193-R201 R231 R232 R292-R302 R325-R327 R331 R333 R334 R342-R344 R415 R500 R1201-R1207 R1209-R1215 R1217-R1231 = R-0402
R50 R51 R71 R338 R345 R346 = R-0603
SW4 = SW-TS24CA
TP1-TP4 = TP-TEST: User Part Number: pn; Tolerance: RichardLC
U1 U2 = U-ETA1654FSG_0
U3 = U-ETA3417S2F
U4 U13-U15 U17-U19 U27 = U-SY6280AAC
U5 = U-HYM8563S
U6 = U-SY7201A_2
U7-U9 = U-ETA5050
U10 = MODULE_AP6XXX
U11 = U-RTL8201F-VB-CG
U21 U22 = U-SP3232EEN
U23 = U-100M-TRANSFORMER
U24 U25 = U-NS4150B
U26 = U-GL850G-60_2
U28 = U-SGM803-SXN3L-TR
XT1 = XTAL-2P
XT2 XT4 XT5 = XTAL-4P

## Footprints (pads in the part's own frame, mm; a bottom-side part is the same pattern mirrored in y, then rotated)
C0402
  rect 0.55x0.55 smd: 1(-0.45,0) 2(0.45,0)
C0603
  rect 0.8x0.9 smd: 1(-0.7,0) 2(0.7,0)
C0805
  rect 0.95x1.3 smd: 1(-0.825,0) 2(0.825,0)
C1206
  rect 1.4x1.6 smd: 1(-1.168,0) 2(1.168,0)
CAPAE660X540
  rect 3.15x1.6 smd: 1(-2.45,0) 2(2.45,0)
DC-044A-2_0-DIP
  round 2.3 hole 2.3 unplated: (4.1,0)
  rect 3x1.6 hole 2x0.8: 2(10.201,5.199) 3(10.201,0) 4(10.201,-3.401)
  rect 2.5x1 hole 2x0.6: 5(3,6.149) 6(3,-3.65)
DFN2510-10L
  rect 0.2x0.68 smd: 1(-1,-0.437) 2(-0.5,-0.437) 4(0.5,-0.437) 5(1,-0.437) 6(1,0.437) 7(0.5,0.437) 9(-0.5,0.437) 10(-1,0.437)
  rect 0.4x0.75 smd: 3(0,-0.395) 8(0,0.395)
FID10X20
  round 1.001 smd: 1(0,0)
FPC05-6P
  rect 0.305x1.27 smd: 1(1.25,1.575) 2(0.75,1.575) 3(0.25,1.575) 4(-0.25,1.575) 5(-0.75,1.575) 6(-1.25,1.575)
  rect 1.803x3.048 smd: 7(2.95,-0.8) 8(-2.95,-0.8)
FPC05-24P
  rect 0.305x1.27 smd: 1(5.75,1.575) 2(5.25,1.575) 3(4.75,1.575) 4(4.25,1.575) 5(3.75,1.575) 6(3.25,1.575) 7(2.75,1.575) 8(2.25,1.575) 9(1.75,1.575) 10(1.25,1.575) 11(0.75,1.575) 12(0.25,1.575) 13(-0.25,1.575) 14(-0.75,1.575) 15(-1.25,1.575) 16(-1.75,1.575) 17(-2.25,1.575) 18(-2.75,1.575) 19(-3.25,1.575) 20(-3.75,1.575) 21(-4.25,1.575) 22(-4.75,1.575) 23(-5.25,1.575) 24(-5.75,1.575)
  rect 1.803x3.048 smd: 25(7.45,-0.8) 26(-7.45,-0.8)
FPC05-30P
  rect 0.305x1.27 smd: 1(7.25,1.575) 2(6.75,1.575) 3(6.25,1.575) 4(5.75,1.575) 5(5.25,1.575) 6(4.75,1.575) 7(4.25,1.575) 8(3.75,1.575) 9(3.25,1.575) 10(2.75,1.575) 11(2.25,1.575) 12(1.75,1.575) 13(1.25,1.575) 14(0.75,1.575) 15(0.25,1.575) 16(-0.25,1.575) 17(-0.75,1.575) 18(-1.25,1.575) 19(-1.75,1.575) 20(-2.25,1.575) 21(-2.75,1.575) 22(-3.25,1.575) 23(-3.75,1.575) 24(-4.25,1.575) 25(-4.75,1.575) 26(-5.25,1.575) 27(-5.75,1.575) 28(-6.25,1.575) 29(-6.75,1.575) 30(-7.25,1.575)
  rect 1.803x3.048 smd: 31(8.95,-0.8) 32(-8.95,-0.8)
FPC05-40P
  rect 0.305x1.27 smd: 1(9.75,1.575) 2(9.25,1.575) 3(8.75,1.575) 4(8.25,1.575) 5(7.75,1.575) 6(7.25,1.575) 7(6.75,1.575) 8(6.25,1.575) 9(5.75,1.575) 10(5.25,1.575) 11(4.75,1.575) 12(4.25,1.575) 13(3.75,1.575) 14(3.25,1.575) 15(2.75,1.575) 16(2.25,1.575) 17(1.75,1.575) 18(1.25,1.575) 19(0.75,1.575) 20(0.25,1.575) 21(-0.25,1.575) 22(-0.75,1.575) 23(-1.25,1.575) 24(-1.75,1.575) 25(-2.25,1.575) 26(-2.75,1.575) 27(-3.25,1.575) 28(-3.75,1.575) 29(-4.25,1.575) 30(-4.75,1.575) 31(-5.25,1.575) 32(-5.75,1.575) 33(-6.25,1.575) 34(-6.75,1.575) 35(-7.25,1.575) 36(-7.75,1.575) 37(-8.25,1.575) 38(-8.75,1.575) 39(-9.25,1.575) 40(-9.75,1.575)
  rect 1.803x3.048 smd: 41(11.45,-0.8) 42(-11.45,-0.8)
HDMI-TYPEA_SMD
  rect 0.3x2.6 smd: 1(0,0) 2(0.5,0) 3(1,0) 4(1.5,0) 5(2,0) 6(2.5,0) 7(3,0) 8(3.5,0) 9(4,0) 10(4.5,0) 11(5,0) 12(5.5,0) 13(6,0) 14(6.5,0) 15(7,0) 16(7.5,0) 17(8,0) 18(8.5,0) 19(9,0)
  oval 1.5x3.5 hole 0.9x2.7: 20(11.75,0.76) 21(-2.75,0.76)
  oval 1.5x2.5 hole 0.9x1.7: 22(-2.75,6.72) 23(11.75,6.72)
IND_252012
  rect 0.7x2 smd: 1(-1.05,0) 2(1.05,0)
IND_404020
  rect 1.5x4 smd: 1(-1.5,0) 2(1.5,0)
IPEX-001E
  rect 1.2x0.8 smd: 1(-1.525,0)
  rect 1.5x1.2 smd: 2(1.8,0)
  rect 2.65x1.2 smd: 3(0,-1.5) 4(0,1.5)
JLX-USB-G36
  rect 0.7x1.6 smd: 1(-3,-0.5) 2(-1,-0.5) 3(1,-0.5) 4(3,-0.5) 5(4,-0.5) 6(2,-0.5) 7(0,-0.5) 8(-2,-0.5) 9(-4,-0.5)
  rect 2x3 smd: 10(-7.25,-1.95) 11(7.25,-1.95) 12(-7.25,-7.95) 13(7.25,-7.95)
L0603
  rect 0.75x0.9 smd: 1(-0.7,0) 2(0.7,0)
LED-SMD_3_2X1_5X1_0
  rect 1.3x0.9 smd: 1(-1.6,0) 2(1.6,0)
  rect 1x0.8 smd: 3(0,0.55)
MSOP-8
  rect 1x0.4 smd: 1(-2.05,0.975) 2(-2.05,0.325) 3(-2.05,-0.325) 4(-2.05,-0.975) 5(2.05,-0.975) 6(2.05,-0.325) 7(2.05,0.325) 8(2.05,0.975)
MTG370_600_VIA
  round 0.95 hole 0.3: (-2.425,0) (-1.715,1.715) (-1.715,-1.715) (0,2.425) (0,-2.425) (1.715,1.715) (1.715,-1.715) (2.425,0) (2.425,0)
  round 6 hole 3.7: 1(0,0)
MX125T-S-2A
  rect 0.5x1.3 smd: 1(-0.625,0) 2(0.625,0)
  rect 2.1x2.4 smd: 3(-3.175,-2.5) 4(3.175,-2.5)
MX125T-S-3A
  rect 0.5x1.3 smd: 1(-1.25,0) 2(0,0) 3(1.25,0)
  rect 2.1x2.4 smd: 4(-3.8,-2.5) 5(3.8,-2.5)
MX125T-S-6A
  rect 0.5x1.3 smd: 1(-3.125,0) 2(-1.875,0) 3(-0.625,0) 4(0.625,0) 5(1.875,0) 6(3.125,0)
  rect 2.1x2.4 smd: 7(-5.675,-2.5) 8(5.675,-2.5)
PB-SIDE-S-3_5X4_5
  round 0.6 hole 0.6 unplated: (-0.851,0.203) (0.851,0.203)
  rect 0.9x1.2 smd: 1(2.301,-0.2) 2(-2.301,-0.2)
  rect 1.15x1.3 smd: 3(1.675,1.35) 4(-1.675,1.35)
PH200-4A
  rect 1.2x1.2 hole 0.8: 1(3,0)
  round 1.2 hole 0.8: 2(1,0) 3(-1,0) 4(-3,0)
PHD200-2X5A
  rect 1.27x1.27 hole 0.813: 1(0,0)
  round 1.27 hole 0.813: 2(0,2) 3(-2,0) 4(-2,2) 5(-4,0) 6(-4,2) 7(-6,0) 8(-6,2) 9(-8,0) 10(-8,2)
PJ-316A-6A
  round 1.397 hole 1.397 unplated: (-10.55,0)
  rect 1.397x1.956 smd: 1(-2.75,3.648) 2(-9.3,-3.648) 3(-5.5,3.648) 4(-2.75,-3.648) 5(-11.5,-3.648) 6(-10.55,3.648)
QFN-28_5X5X05P
  custom 0.075x0.075 smd: 1(-2.55,1.5) 2(-2.55,1) 3(-2.55,0.5) 4(-2.55,0) 5(-2.55,-0.5) 6(-2.55,-1) 7(-2.55,-1.5) 8(-1.5,-2.55) 9(-1,-2.55) 10(-0.5,-2.55) 11(0,-2.55) 12(0.5,-2.55) 13(1,-2.55) 14(1.5,-2.55) 15(2.55,-1.5) 16(2.55,-1) 17(2.55,-0.5) 18(2.55,0) 19(2.55,0.5) 20(2.55,1) 21(2.55,1.5) 22(1.5,2.55) 23(1,2.55) 24(0.5,2.55) 25(0,2.55) 26(-0.5,2.55) 27(-1,2.55) 28(-1.5,2.55)
  custom 0.912x0.912 smd: 29(0,0)
QFN-32_5X5X05P
  custom 0.07x0.07 smd: 1(-2.4,1.751) 2(-2.4,1.251) 3(-2.4,0.751) 4(-2.4,0.25) 5(-2.4,-0.25) 6(-2.4,-0.751) 7(-2.4,-1.251) 8(-2.4,-1.751) 9(-1.751,-2.4) 10(-1.251,-2.4) 11(-0.751,-2.4) 12(-0.25,-2.4) 13(0.25,-2.4) 14(0.751,-2.4) 15(1.251,-2.4) 16(1.751,-2.4) 17(2.4,-1.751) 18(2.4,-1.251) 19(2.4,-0.751) 20(2.4,-0.25) 21(2.4,0.25) 22(2.4,0.751) 23(2.4,1.251) 24(2.4,1.751) 25(1.751,2.4) 26(1.251,2.4) 27(0.751,2.4) 28(0.25,2.4) 29(-0.25,2.4) 30(-0.751,2.4) 31(-1.251,2.4) 32(-1.751,2.4)
  rect 3.607x3.607 smd: 33(0,0)
R0402
  rect 0.55x0.55 smd: 1(-0.45,0) 2(0.45,0)
R0603
  rect 0.65x0.8 smd: 1(-0.725,0) 2(0.725,0)
RJ45_SMD_1188N
  rect 0.5x3.8 smd: 1(3.57,11.2) 2(2.55,11.2) 3(1.53,11.2) 4(0.51,11.2) 5(-0.51,11.2) 6(-1.53,11.2) 7(-2.55,11.2) 8(-3.57,11.2)
  rect 1x3.5 smd: 9(-7,11.6) 10(-4.65,11.6) 11(4.65,11.6) 12(7,11.6)
  oval 0.8x2.6 hole 0.4x2.2: 13(-8,4.3) 14(8,4.3)
SMAF
  rect 1.43x1.53 smd: A(-1.84,0) C(1.84,0)
SMB_DO-214AA
  rect 1.65x1.95 smd: A(2.2,0) C(-2.2,0)
SMD1812
  rect 2.032x3.302 smd: 1(-2.159,0) 2(2.159,0)
SOD123
  rect 0.8x0.75 smd: A(1.7,0) C(-1.7,0)
SOD523
  rect 0.65x0.5 smd: A(0.9,0) C(-0.9,0)
SOD-123F
  rect 0.94x0.95 smd: A(-1.55,0) C(1.55,0)
SOM3566-239P
  oval 0.559x1.3 smd: 1(1.5,0) 2(2.5,0) 3(3.5,0) 4(4.5,0) 5(5.5,0) 6(6.5,0) 7(7.5,0) 8(8.5,0) 9(9.5,0) 10(10.5,0) 11(11.5,0) 12(12.5,0) 13(13.5,0) 14(14.5,0) 15(15.5,0) 16(16.5,0) 17(17.5,0) 18(18.5,0) 19(19.5,0) 20(20.5,0) 21(21.5,0) 22(22.5,0) 23(23.5,0) 24(24.5,0) 25(25.5,0) 26(26.5,0) 27(27.5,0) 28(28.5,0) 29(29.5,0) 30(30.5,0) 31(31.5,0) 32(32.5,0) 33(33.5,0) 34(34.5,0) 35(35.5,0) 36(36.5,0) 37(37.5,0) 38(38.5,0) 39(39.5,0) 40(40.5,0) 41(41.5,0) 42(42.5,0) 43(43.5,0) 44(44.5,0) 45(45.5,0) 46(46.5,0) 47(47.5,0) 48(48.5,0) 87(48.5,40) 88(47.5,40) 89(46.5,40) 90(45.5,40) 91(44.5,40) 92(43.5,40) 93(42.5,40) 94(41.5,40) 95(40.5,40) 96(39.5,40) 97(38.5,40) 98(37.5,40) 99(36.5,40) 100(35.5,40) 101(34.5,40) 102(33.5,40) 103(32.5,40) 104(31.5,40) 105(30.5,40) 106(29.5,40) 107(28.5,40) 108(27.5,40) 109(26.5,40) 110(25.5,40) 111(24.5,40) 112(23.5,40) 113(22.5,40) 114(21.5,40) 115(20.5,40) 116(19.5,40) 117(18.5,40) 118(17.5,40) 119(16.5,40) 120(15.5,40) 121(14.5,40) 122(13.5,40) 123(12.5,40) 124(11.5,40) 125(10.5,40) 126(9.5,40) 127(8.5,40) 128(7.5,40) 129(6.5,40) 130(5.5,40) 131(4.5,40) 132(3.5,40) 133(2.5,40) 134(1.5,40)
  oval 1.3x0.559 smd: 49(50,1.5) 50(50,2.5) 51(50,3.5) 52(50,4.5) 53(50,5.5) 54(50,6.5) 55(50,7.5) 56(50,8.5) 57(50,9.5) 58(50,10.5) 59(50,11.5) 60(50,12.5) 61(50,13.5) 62(50,14.5) 63(50,15.5) 64(50,16.5) 65(50,17.5) 66(50,18.5) 67(50,19.5) 68(50,20.5) 69(50,21.5) 70(50,22.5) 71(50,23.5) 72(50,24.5) 73(50,25.5) 74(50,26.5) 75(50,27.5) 76(50,28.5) 77(50,29.5) 78(50,30.5) 79(50,31.5) 80(50,32.5) 81(50,33.5) 82(50,34.5) 83(50,35.5) 84(50,36.5) 85(50,37.5) 86(50,38.5) 135(0,38.5) 136(0,37.5) 137(0,36.5) 138(0,35.5) 139(0,34.5) 140(0,33.5) 141(0,32.5) 142(0,31.5) 143(0,30.5) 144(0,29.5) 145(0,28.5) 146(0,27.5) 147(0,26.5) 148(0,25.5) 149(0,24.5) 150(0,23.5) 151(0,22.5) 152(0,21.5) 153(0,20.5) 154(0,19.5) 155(0,18.5) 156(0,17.5) 157(0,16.5) 158(0,15.5) 159(0,14.5) 160(0,13.5) 161(0,12.5) 162(0,11.5) 163(0,10.5) 164(0,9.5) 165(0,8.5) 166(0,7.5) 167(0,6.5) 168(0,5.5) 169(0,4.5) 170(0,3.5) 171(0,2.5) 172(0,1.5)
  rect 1.5x1.5 smd: 173(3.05,3.05) 174(6.05,3.05) 175(9.05,3.05) 176(12.05,3.05) 177(15.05,3.05) 178(18.05,3.05) 179(21.05,3.05) 180(25,3.05) 181(28.95,3.05) 182(31.95,3.05) 183(34.95,3.05) 184(37.95,3.05) 185(40.95,3.05) 186(43.95,3.05) 187(46.95,3.05) 188(46.95,6.05) 189(46.95,9.05) 190(46.95,12.05) 191(46.95,15.05) 192(46.95,18.5) 193(46.95,21.95) 194(46.95,24.95) 195(46.95,27.95) 196(46.95,30.95) 197(46.95,33.95) 198(46.95,36.95) 199(43.95,36.95) 200(40.95,36.95) 201(37.95,36.95) 202(34.95,36.95) 203(31.95,36.95) 204(28.95,36.95) 205(25,36.95) 206(21.05,36.95) 207(18.05,36.95) 208(15.05,36.95) 209(12.05,36.95) 210(9.05,36.95) 211(6.05,36.95) 212(3.05,36.95) 213(3.05,33.95) 214(3.05,30.95) 215(3.05,27.95) 216(3.05,24.95) 217(3.05,21.95) 218(3.05,18.5) 219(3.05,15.05) 220(3.05,12.05) 221(3.05,9.05) 222(3.05,6.05) 223(9.05,6.05) 224(12.05,6.05) 225(31.95,6.05) 226(34.95,6.05) 227(37.95,6.05) 228(40.95,6.05) 229(43.95,6.05) 230(43.95,9.05) 231(43.95,12.05) 232(43.95,33.95) 233(6.05,33.95) 234(6.05,30.95) 235(6.05,27.95) 236(6.05,24.95) 237(6.05,21.95) 238(9.05,9.05) 239(12.05,9.05)
SOP16-P127-710X1270
  oval 1.8x0.6 smd: 1(-4.3,4.445) 2(-4.3,3.175) 3(-4.3,1.905) 4(-4.3,0.635) 5(-4.3,-0.635) 6(-4.3,-1.905) 7(-4.3,-3.175) 8(-4.3,-4.445) 9(4.3,-4.445) 10(4.3,-3.175) 11(4.3,-1.905) 12(4.3,-0.635) 13(4.3,0.635) 14(4.3,1.905) 15(4.3,3.175) 16(4.3,4.445)
SOT23
  rect 1.05x0.65 smd: 1(-1.15,0.95) 2(-1.15,-0.95) 3(1.15,0)
SOT23-5
  rect 1.1x0.6 smd: 1(-1.35,0.95) 2(-1.35,0) 3(-1.35,-0.95) 4(1.35,-0.95) 5(1.35,0.95)
SOT23-6
  rect 1.05x0.6 smd: 1(-1.35,0.95) 2(-1.35,0) 3(-1.35,-0.95) 4(1.35,-0.95) 5(1.35,0) 6(1.35,0.95)
SOT523
  rect 0.85x0.3 smd: 1(-0.8,0.5) 2(-0.8,-0.5) 3(0.8,0)
SOT563
  rect 0.47x0.26 smd: 1(0.36,-0.6) 2(0.36,-1.1) 3(0.36,-1.6) 4(1.84,-1.6) 5(1.84,-1.1) 6(1.84,-0.6)
TF-01A
  round 1 hole 1: (-7.2,-10.5) (0.8,-10.5)
  oval 0.7x2.3 smd: 1(0,0.2) 2(-1.1,0.2) 3(-2.2,0.2) 4(-3.3,0.2) 5(-4.4,0.2) 6(-5.5,0.2) 7(-6.6,0.2) 8(-7.7,0.2) 9(-8.8,0.2)
  rect 1.2x1.4 smd: 10(-10,-0.5)
  rect 1.6x1.4 smd: 11(4.6,-0.5)
  rect 1.2x2.2 smd: 12(-10,-10.2) 13(5.5,-10.2)
TP80
  round 0.8 smd: 1(0,0)
TP100
  round 1 smd: 1(0,0)
TSSOP-8
  rect 1.905x0.381 smd: 1(-2.1,0.975) 2(-2.1,0.325) 3(-2.1,-0.325) 4(-2.1,-0.975) 5(2.1,-0.975) 6(2.1,-0.325) 7(2.1,0.325) 8(2.1,0.975)
TSSOP-16
  rect 1.45x0.45 smd: 1(-2.901,2.276) 2(-2.901,1.626) 3(-2.901,0.975) 4(-2.901,0.325) 5(-2.901,-0.325) 6(-2.901,-0.975) 7(-2.901,-1.626) 8(-2.901,-2.276) 9(2.901,-2.276) 10(2.901,-1.626) 11(2.901,-0.975) 12(2.901,-0.325) 13(2.901,0.325) 14(2.901,0.975) 15(2.901,1.626) 16(2.901,2.276)
USB_4A_SMD
  round 1.3 hole 1.3 unplated: (-2.45,-4.4) (2.45,-4.4)
  rect 0.9x2.1 smd: 1(-3.5,-0.3) 2(-1,-0.3) 3(1,-0.3) 4(3.5,-0.3)
  rect 2.5x5 smd: 5(-7.3,-3.15) 6(7.3,-3.15)
V0402
  rect 0.57x0.62 smd: 1(-0.48,0) 2(0.48,0)
WIFI_44P_12X12
  rect 1.2x0.5 smd: 1(-5.7,4.5) 2(-5.7,3.6) 3(-5.7,2.7) 4(-5.7,1.8) 5(-5.7,0.9) 6(-5.7,0) 7(-5.7,-0.9) 8(-5.7,-1.8) 9(-5.7,-2.7) 10(-5.7,-3.6) 11(-5.7,-4.5) 23(5.7,-4.5) 24(5.7,-3.6) 25(5.7,-2.7) 26(5.7,-1.8) 27(5.7,-0.9) 28(5.7,0) 29(5.7,0.9) 30(5.7,1.8) 31(5.7,2.7) 32(5.7,3.6) 33(5.7,4.5)
  rect 0.5x1.2 smd: 12(-4.5,-5.7) 13(-3.6,-5.7) 14(-2.7,-5.7) 15(-1.8,-5.7) 16(-0.9,-5.7) 17(0,-5.7) 18(0.9,-5.7) 19(1.8,-5.7) 20(2.7,-5.7) 21(3.6,-5.7) 22(4.5,-5.7) 34(4.5,5.7) 35(3.6,5.7) 36(2.7,5.7) 37(1.8,5.7) 38(0.9,5.7) 39(0,5.7) 40(-0.9,5.7) 41(-1.8,5.7) 42(-2.7,5.7) 43(-3.6,5.7) 44(-4.5,5.7)
  round 0.6 smd: 45(-2.7,3.6) 46(-0.9,3.6) 47(0.9,3.6)
XTAL_32X15_2P
  rect 0.85x1.6 smd: 1(-1.25,0) 2(1.25,0)
XTAL_32X25_4P
  rect 1.2x1.3 smd: 1(-0.9,1.2) 2(-0.9,-1.2) 3(0.9,-1.2) 4(0.9,1.2)

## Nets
GND: C1.2 C4.1 C5.1 C7.1 C8.1 C9.1 C10.1 C11.1 C12.1 C14.1 C15.1 C16.1 C17.1 C18.1 C20.1 C21.1 C22.1 C23.1 C24.1 C25.1 C26.1 C27.1 C28.1 C29.1 C30.1 C31.1 C32.1 C33.1 C40.1 C41.1 C42.1 C43.1 C47.1 C48.1 C49.1 C50.1 C51.1 C53.1 C54.1 C55.1 C57.1 C58.1 C59.1 C60.1 C61.2 C62.1 C63.1 C64.1 C67.1 C68.1 C72.1 C73.1 C76.1 C78.2 C79.1 C80.1 C81.1 C82.1 C83.1 C85.1 C86.1 C90.1 C91.1 C123.2 C124.2 C129.1 C131.1 C145.1 C146.1 C150.1 C151.1 C153.1 C154.1 C155.1 C156.1 C158.1 C159.1 C161.1 C175.1 C178.1 C179.1 C180.1 C183.1 C184.1 C185.1 C186.1 C188.1 C192.2 C193.2 C194.1 C196.1 C197.2 C198.2 C202.1 C203.1 C298.1 C322.1 C324.1 C333.1 C334.1 C341.1 C343.1 C344.1 C346.1 C357.1 C358.1 C359.1 C360.1 C361.1 C362.1 C363.1 C369.1 C370.1 C371.1 C372.1 C380.1 C381.1 C383.1 C384.1 C385.1 C386.2 C387.1 C388.1 C389.1 C390.1 C391.1 C392.1 C393.2 C397.1 D1.A D2.C(I/O1) D5.2(I/O1) D6.3 D6.8 D7.3 D7.8 D8.2(I/O1) D9.2(I/O1) D10.2(I/O1) D11.2(I/O1) D18.3 D18.8 D26.1(I/O2) D27.2(I/O1) D28.1(I/O2) D29.2(I/O1) D30.3 D30.8 D31.3 D31.8 D32.3 D32.8 D33.3 D33.8 D34.3 D34.8 D35.1(I/O2) D36.1(I/O2) D37.2(I/O1) D38.2(I/O1) D39.2(I/O1) D40.2(I/O1) D41.2(I/O1) D43.3 D43.8 D44.3 D44.8 D45.3 D45.8 D46.2(I/O1) D47.2(I/O1) D81.2 D82.3 D82.8 J1.2 J1.3 J1.5(TH1) J1.6(TH2) J2.1 J2.2 J3.2 J3.3 J3.4 J5.10 J5.11 J5.12 J5.13 J5.15 J5.16 J5.20 J5.23 J5.26 J5.29 J5.31 J5.32 J6.2 J6.5 J6.8 J6.11 J6.17 J6.20 J6.21 J6.22 J6.23 J7.10 J7.13 J7.16 J7.19 J7.22 J7.25 J7.28 J7.31 J7.32 J7.33 J7.41 J7.42 J8.11 J8.16 J8.18 J8.19 J8.22 J8.25 J8.28 J8.31 J8.34 J8.37 J8.41 J8.42 J9.6 J9.7 J9.8 J10.10 J10.13 J10.16 J10.19 J10.22 J10.25 J10.26 J11.1(GND1) J11.3(GND2) J11.4(GND3) J13.4 J15.4(GND) J15.5(SGND1) J15.6(SGND2) J16.4(GND) J16.7(DGND) J16.10(TH1) J16.11(TH2) J16.12 J16.13 J21.6(VSS) J21.10(G1) J21.11(G2) J21.12(G3) J21.13(G4) J22.3 J22.4 J22.5 J31.10 J36.4 J37.4 J38.4 J39.4 J40.4 J41.4 J42.4 J43.4 J45.2 J45.3 J45.4 J46.6 J46.7 J46.8 M1.170(GND1) M1.176(GND2) M1.181(GND3) M1.186(GND4) M1.187(GND5) M1.188(GND6) M1.192(GND7) M1.197(GND8) M1.198(GND9) M1.199(GND10) M1.205(GND11) M1.211(GND12) M1.212(GND13) M1.213(GND14) M1.218(GND15) M1.223(GND16) M1.224(GND17) M1.229(GND18) M1.232(GND19) M1.233(GND20) M1.238(GND21) M1.239(GND22) Q5.2(SOURCE) Q10.2(SOURCE) R7.1 R8.1 R9.1 R12.1 R17.1 R20.1 R30.1 R49.1 R50.1 R51.1 R57.1 R60.1 R64.1 R69.2 R119.2 R122.1 R123.1 R129.1 R136.2 R148.2 R153.2 R158.2 R165.1 R199.1 R231.1 R295.1 R327.2 R331.2 R500.2 R1207.2 R1209.1 R1210.1 R1212.2 R1214.2 R1215.2 R1217.1 R1220.1 SW4.1 SW4.2 SW4.4 TP4.1 U1.3(GND) U2.3(GND) U3.2(GND) U4.2(GND) U5.4(VSS) U6.2(GND) U7.2(GND) U8.2(GND) U9.2(GND) U10.1(GND1) U10.3(GND2) U10.20(GND3) U10.31(GND4) U10.33(GND5) U10.36(GND6) U11.33(E-PAD) U13.2(GND) U14.2(GND) U15.2(GND) U17.2(GND) U18.2(GND) U19.2(GND) U21.15(GND) U22.15(GND) U24.7(GND) U25.7(GND) U26.29(GND) U27.2(GND) U28.1(GND) XT2.2 XT2.4 XT4.2 XT4.4 XT5.2 XT5.4
GND_EARTH: C395.1 C396.1 HOLE1.1 J12.13(SH1) J12.14(SH2)
VBAT_RTC: D4.A J3.1
VBAT_WL_1T1R: C82.2 C83.2 R71.2 U10.9(VBAT)
VCC1V5_DVP: C73.2 C394.2 J10.3 R63.2 U9.5(VOUT)
VCC1V8_DVP: C68.2 J10.4 Q8.1(GATE) Q9.1(GATE) R59.2 R1222.2 R1223.2 U8.5(VOUT)
VCC2V8_DVP: C64.2 J10.1 J10.2 R56.2 U7.5(VOUT)
VCC3V3_SD_OUT: C156.2 J21.4(VDD) M1.38(VCC3V3_SD_OUT)
VCC3V3_SYS: C21.2 C22.2 C23.2 C54.2 D3.A J46.1 L3.2 R10.2 R21.2 R22.2 R38.1 R40.2 R42.2 R46.1 R71.1 U4.5(IN)
VCC5V0_USB_FE_D1: C129.2 J13.1 U15.1(VOUT)
VCC5V0_USB_FE_D2: C145.2 J36.1 U17.1(VOUT)
VCC5V0_USB_FE_D3: C150.2 J37.1 U18.1(VOUT)
VCC5V0_USB_FE_D4: C153.2 J38.1 U19.1(VOUT)
VCC5V0_USB_HOST1: C344.2 C346.2 J16.1(VBUS) U14.1(VOUT)
VCC5V0_USB_HOST2: C358.2 J39.1 U27.1(VOUT)
VCC5V0_USB_OTG: C341.2 C343.2 J15.1(VCC) R121.2 U13.1(VOUT)
VCC5V_HDMI_TX: C47.2 D13.C J6.18
VCC5V_SYS: C6.2 C7.2 C8.2 C10.2 C18.2 C20.2 C27.2 C28.2 C369.2 C370.2 D2.A(I/O2) L1.2 M1.171(VCC5V0_SYS_IN2) M1.172(VCC5V0_SYS_IN1) R3.2 R18.2 R47.1 R232.2 R500.1 U3.4(VIN)
VCC-AMP: C359.2 C360.2 C361.2 C362.2 R338.2 U24.6(VCC) U25.6(VCC)
VCC_1V8_OUT: C85.2 C86.2 M1.166(VCC_1V8_OUT) R6.1 R14.2 R65.1 R66.1 R73.1 U10.22(VDDIO)
VCC_3V3_HUB: C298.2 C322.2 C324.2 C334.2 R292.2 R293.2 R294.2 R296.1 R297.1 R300.2 R301.2 R302.2 R345.2 U26.14(AVDD33) U26.21(VDD33#21) U26.28(VDD33#28)
VCC_5V: C13.2 C14.2 C15.2 C16.2 C57.2 C59.2 C123.1 C124.1 C131.2 C146.2 C151.2 C154.2 C357.2 C363.2 D12.A D13.A J40.1 J41.1 J42.1 J43.1 L2.2 L5.1 Q1.1(GATE) R4.2 R195.1 R338.1 R346.1 U6.6(VIN) U13.5(IN) U14.5(IN) U15.5(IN) U17.5(IN) U18.5(IN) U19.5(IN) U27.5(IN)
VCC_12V: C1.1 C4.2 C5.2 C9.2 C11.2 C12.2 C17.2 C42.2 C43.2 C50.2 C51.2 D1.C F1.2 J5.2 J5.3 J5.4 J5.5 J7.38 J7.39 J7.40 R5.1 U1.1(IN) U2.1(IN)
VCC_DCIN: F1.1 J1.4 J2.3 J2.4
VCC_LEDA_TX1: C58.2 C60.2 D23.C J8.1 J8.2 U6.5(OVP)
VCC_LEDK_TX1: J8.9 J8.10 R48.1 R50.2 R51.2
VCC_RMII: C381.2 C391.2 R1202.2 R1203.2 R1204.1 R1211.1 R1213.2 R1218.1 R1219.2 R1225.1 R1226.2 U11.14(DVDD33)
VCCA_RMII: C380.2 C389.2 C390.2 R1225.2 U11.7(AVDD33_1) U11.30(AVDD33_2)
VCCIO5_IN: C26.2 C29.2 M1.83(VCCIO6_IN) M1.84(VCCIO5_IN) M1.228(VCC_3V3_OUT)
VDD_3V3: C24.2 C25.2 C40.2 C41.2 C48.2 C49.2 C55.2 C63.2 C67.2 C72.2 C175.2 C180.2 J5.18 J5.19 J7.2 J7.3 J8.38 J8.39 Q2.1(GATE) Q3.1(GATE) R19.1 R29.2 R31.1 R33.1 R163.1 R164.2 R170.2 R193.2 R194.2 R196.1 R333.1 R334.1 R344.1 R345.1 R415.1 R1226.1 R1230.1 U4.1(VOUT) U7.1(VIN) U8.1(VIN) U9.1(VIN) U21.16(VCC) U22.16(VCC)
VDD_RTC: C32.2 D3.C D4.C U5.8(VDD)
VDD_USB_5V: C333.2 R346.2 U26.27(V5)
CAM_CLKOUT0_MIPI_CSI: C62.2 J10.9 R16.1 R17.2
CIF_SCL: J10.7 Q8.2(SOURCE) R1222.1
CIF_SDA: J10.8 Q9.2(SOURCE) R1223.1
CKXTALIN: C386.1 U11.32(CKXTAL-IN) XT4.3
CKXTALOUT: C387.2 U11.31(CKXTAL-OUT) XT4.1
COLOR_ENABLE: J5.6 TP2.1
EDP_HPDIN_M1: J5.14 M1.158(PWM3_IR/EDP_HPDIN_M1/MCU_JTAG_T)
EDP_ON: J5.9 M1.94(VOP_BT1120_D6/ETH1_REFCLKO_25M_)
EDP_TX_AUXN: C34.2 M1.22(EDP_TX_AUXN)
EDP_TX_AUXN_: C34.1 J5.21
EDP_TX_AUXP: C35.2 M1.23(EDP_TX_AUXP)
EDP_TX_AUXP_: C35.1 J5.22
EDP_TX_D0N: C38.2 M1.30(EDP_TX_D0N)
EDP_TX_D0N_: C38.1 J5.25
EDP_TX_D0P: C39.2 M1.31(EDP_TX_D0P)
EDP_TX_D0P_: C39.1 J5.24
EDP_TX_D1N: C36.2 M1.28(EDP_TX_D1N)
EDP_TX_D1N_: C36.1 J5.28
EDP_TX_D1P: C37.2 M1.29(EDP_TX_D1P)
EDP_TX_D1P_: C37.1 J5.27
FE1.1_DM1: R131.1 U26.3(DM1)
FE1.1_DM1_: D31.1 D31.10 J13.2 R131.2
FE1.1_DM2: R146.1 U26.6(DM2)
FE1.1_DM2_: D31.4 D31.7 J36.2 R146.2
FE1.1_DM3: R151.1 U26.12(DM3)
FE1.1_DM3_: D32.1 D32.10 J37.2 R151.2
FE1.1_DM4: R156.1 U26.15(DM4)
FE1.1_DM4_: D32.4 D32.7 J38.2 R156.2
FE1.1_DP1: R132.1 U26.4(DP1)
FE1.1_DP1_: D31.2 D31.9 J13.3 R132.2
FE1.1_DP2: R149.1 U26.7(DP2)
FE1.1_DP2_: D31.5 D31.6 J36.3 R149.2
FE1.1_DP3: R154.1 U26.13(DP3)
FE1.1_DP3_: D32.2 D32.9 J37.3 R154.2
FE1.1_DP4: R159.1 U26.16(DP4)
FE1.1_DP4_: D32.5 D32.6 J38.3 R159.2
FE1_1_DM0: R299.2 U26.1(DMU)
FE1_1_XIN: C203.2 U26.10(X1) XT5.1
FE1_1_XOUT: C202.2 U26.11(X2) XT5.3
FE2_1_DP0: R298.2 U26.2(DPU)
GMAC1_MCLKINOUT_M0: C383.2 M1.79(PWM13_M0/GMAC1_MCLKINOUT_M0/UAR) R1224.1
GMAC1_MDC_M0: M1.77(PWM14_M0/VOP_PWM_M1/GMAC1_MDC_M) U11.22(MDC)
GMAC1_MDIO_M0: M1.76(PWM15_IR_M0/SPDIF_TX_M1/GMAC1_M) R1204.2 U11.23(MDIO)
GMAC1_RSTN: M1.82(VOP_BT1120_D13/SPI1_MOSI_M1/PCI) R1201.1
GMAC1_RXD0_M0: M1.92(PWM8_M0/VOP_BT1120_D7/GMAC1_RXD) R1206.2
GMAC1_RXD1_M0: M1.93(PWM9_M0/VOP_BT1120_D8/GMAC1_RXD) R1205.2
GMAC1_RXDV_CRS_M0: M1.88(VOP_BT1120_D9/I2C5_SCL_M0/GMAC1) R1209.2 U11.26(CRS/CRS_DV)
GMAC1_RXER_M0: M1.87(VOP_BT1120_D10/I2C5_SDA_M0/GMAC) R1212.1 U11.28(RXER/FXEN)
GMAC1_TXD0_M0: M1.86(PWM10_M0/VOP_BT1120_D11/I2C3_SC) U11.16(TXD0)
GMAC1_TXD1_M0: M1.85(PWM11_IR_M0/VOP_BT1120_D12/I2C3) U11.17(TXD1)
GMAC1_TXEN_M0: M1.78(PWM12_M0/GMAC1_TXEN_M0/UART3_TX) U11.20(TXEN)
GPIO0_A5_USB_OTG_PWREN: M1.215(SDMMC0_PWREN/SATA_MP_SWITCH/PCI) R117.2 U13.4(EN)
GPIO0_A6_USB_OTG0_DET: M1.216(GPU_PWREN/SATA_CP_POD/GPIO0_A6_) R120.1
GPIO0_B0_U_TP_INT_L: M1.161(CLK32K_IN/CLK32K_OUT0/GPIO0_B0_) R44.1
GPIO0_C7_D_TP_RST_L: M1.154(PWM0_M1/HDMITX_CEC_M1/UART0_CTS) R43.1
GPIO0_D3_CIF_PDN_L: J10.6 M1.217(GPIO0_D3_D)
GPIO2_B1_WIFI_REG_ON_H: M1.52(UART8_RTSN_M0/I2C4_SDA_M1/SDMMC) U10.12(WL_REG_ON)
GPIO2_B2_WIFI_WAKE_HOST_H: M1.53(UART8_CTSN_M0/I2C4_SCL_M1/SDMMC) U10.13(WL_HOST_WAKE)
GPIO2_B7_BT_REG_ON_H: M1.225(UART6_RTSN_M0/SPI1_MOSI_M0/I2S2) U10.34(BT_RST_N)
GPIO2_C0_BT_WAKE_HOST_H: M1.182(UART6_CTSN_M0/SPI1_CS0_M0/I2S2_) U10.7(BT_HOST_WAKE)
GPIO2_C1_HOST_WAKE_BT_H: M1.226(UART7_RTSN_M0/SPI2_CLK_M0/ETH0_) U10.6(BT_WAKE)
GPIO2_C6_CIF_RST_L: J10.5 M1.43(UART8_RX_M0/SPI1_CS1_M0/CLK32K_)
GPIO3_D6_SPK_CTRL_L: M1.75(CIF_D8/EBC_SDDO8/GMAC1_TXD2_M1/) R199.2 U24.1(CTRL) U25.1(CTRL)
GPIO3_D7_LVDS_ON: J7.36 M1.74(CIF_D9/EBC_SDDO9/GMAC1_TXD3_M1/)
GPIO4_A0_MIPI_TX1_RST_L: M1.72(CIF_D10/EBC_SDDO10/GMAC1_TXCLK_) R342.1
GPIO4_B0_USB_HOST1_PWREN_H: M1.58(CAM_CLKOUT1/EBC_SDCE2/GMAC1_RXD) U14.4(EN)
GPIO4_B1_CIF_PWREN_H: M1.70(ISP_PRELIGHT_TRIG/EBC_SDCE3/GMA) R1221.1
GPIO4_B4_USB_FE_D4_PWREN_H: M1.68(ISP_FLASH_TRIGIN/I2C2_SDA_M1/EB) U19.4(EN)
GPIO4_B5_HUB_XRSTJ: M1.67(I2C2_SCL_M1/EBC_SDSHR/I2S1_SDO3) R343.2
GPIO4_B6_USB_FE_D2_PWREN_H: M1.59(CIF_HREF/EBC_SDLE/GMAC1_MDC_M1/) U17.4(EN)
GPIO4_B7_USB_FE_D3_PWREN_H: M1.64(CIF_VSYNC/EBC_SDOE/GMAC1_MDIO_M) U18.4(EN)
GPIO4_C0_USB_HOST2_PWREN_H: M1.60(PWM11_IR_M1/CIF_CLKOUT/EBC_GDCL) U27.4(EN)
GPIO4_C1_USB_FE_D1_PWREN_H: M1.66(CIF_CLKIN/EBC_SDCLK/GMAC1_MCLKI) U15.4(EN)
HDMI_TX_CEC_PORT: D9.1(I/O2) J6.13 Q1.3(DRAIN)
HDMI_TX_CLKN: D7.5 D7.6 J6.12 M1.139(HDMI_TX_CLKN)
HDMI_TX_CLKP: D7.4 D7.7 J6.10 M1.140(HDMI_TX_CLKP)
HDMI_TX_D0N: D7.2 D7.9 J6.9 M1.141(HDMI_TX_D0N)
HDMI_TX_D0P: D7.1 D7.10 J6.7 M1.142(HDMI_TX_D0P)
HDMI_TX_D1N: D6.5 D6.6 J6.6 M1.143(HDMI_TX_D1N)
HDMI_TX_D1P: D6.4 D6.7 J6.4 M1.144(HDMI_TX_D1P)
HDMI_TX_D2N: D6.2 D6.9 J6.3 M1.145(HDMI_TX_D2N)
HDMI_TX_D2P: D6.1 D6.10 J6.1($PIN0) M1.146(HDMI_TX_D2P)
HDMI_TX_HPD_PORT: D8.1(I/O2) J6.19 R28.2 R30.2
HDMI_TX_HPDIN: M1.135(HDMI_TX_HPDIN) R28.1
HDMI_TXDDC_SCL_PORT: D10.1(I/O2) J6.15 Q2.3(DRAIN) R32.2
HDMI_TXDDC_SDA_PORT: D11.1(I/O2) J6.16 Q3.3(DRAIN) R34.2
HDMITX_CEC_M0: M1.138(HDMITX_CEC_M0/SPI3_CS1_M1/GPIO4) Q1.2(SOURCE) R29.1
HDMITX_SCL: M1.137(HDMITX_SCL/I2C5_SCL_M1/GPIO4_C7) Q2.2(SOURCE) R31.2
HDMITX_SDA: M1.136(HDMITX_SDA/I2C5_SDA_M1/GPIO4_D0) Q3.2(SOURCE) R33.2
HP_DET_L: M1.89(VOP_BT1120_D5/GMAC1_RXCLK_M0/SD) R166.1
HP_SNS: J34.4(GND) M1.8(HP_SNS) R165.2
HPL_OUT: C157.2 C187.1 M1.7(HPL_OUT)
HPL_OUT+: C157.1 D37.1(I/O2) J34.2(L) R331.1
HPR_OUT: C160.2 C195.1 M1.9(HPR_OUT)
HPR_OUT+: C160.1 D39.1(I/O2) J34.3(R)
HUB_RSTJ: R343.1 U26.17(RESET#CDP)
I2C1_SCL_TP: M1.160(I2C1_SCL/MCU_JTAG_TDO/GPIO0_B3_) R41.1
I2C1_SDA_TP: M1.159(I2C1_SDA/PCIE20_BUTTONRSTN/MCU_) R39.1
I2C2_SCL_M0_RTC: M1.149(PWM1_M1/I2C2_SCL_M0/SPI0_CLK_M0) R22.1 R23.2
I2C2_SDA_M0_RTC: M1.147(PWM2_M1/I2C2_SDA_M0/SPI0_MOSI_M) R21.1 R24.2
I2C3_SCL_M0_OUT: D45.5 D45.6 J31.8 M1.200(I2C3_SDA_M0/UART3_RX_M0/AUDIOPW) R194.1
I2C3_SDA_M0_OUT: D45.4 D45.7 J31.6 M1.196(I2C3_SCL_M0/UART3_TX_M0/AUDIOPW) R193.1
I2C4_SCL_M0_MIPI CSI: M1.65(I2C4_SCL_M0/EBC_GDOE/ETH1_REFCL) Q8.3(DRAIN) R334.2
I2C4_SDA_M0_MIPI CSI: M1.63(I2C4_SDA_M0/EBC_VCOM/GMAC1_RXER) Q9.3(DRAIN) R333.2
I2C_SCL_RTC: R23.1 U5.6(SCL)
I2C_SDA_RTC: R24.1 U5.5(SDA)
I2S2_LRCK_TX_M0_WIFI: M1.45(UART9_RTSN_M0/SPI2_MOSI_M0/I2S2) U10.28(PCM_SYNC)
I2S2_SCLK_TX_M0_WIFI: M1.42(UART7_CTSN_M0/SPI2_MISO_M0/I2S2) U10.26(PCM_CLK)
I2S2_SDI_M0_WIFI: M1.41(UART8_TX_M0/SPI2_CS1_M0/I2S2_SD) U10.25(PCM_OUT)
I2S2_SDO_M0_WIFI: M1.44(UART9_CTSN_M0/SPI2_CS0_M0/I2S2_) U10.27(PCM_IN)
LCD_SELF_TEST: J5.17 TP1.1
LED0/PHYAD0: C392.2 J12.10(LEDY-) R1218.2 U11.24(LED0/PHYAD0/PMEB)
LED1/PHYAD1: C393.1 J12.11(LEDG+) R1217.2 U11.25(LED1/PHYAD1)
MIC_IN1: C365.1 D40.1(I/O2) J34.1(MIC) R169.1
MIC_IN2: C366.1 D41.1(I/O2) J45.1 R167.1 TP3.1
MIC_L_IN: C366.2 M1.10(MIC1P/MIC_L)
MIC_R_IN: C365.2 M1.11(MIC1N/MIC_R)
MIPI_CSI_RX_CLK0N: J10.17 M1.105(MIPI_CSI_RX_CLK0N)
MIPI_CSI_RX_CLK0P: J10.18 M1.106(MIPI_CSI_RX_CLK0P)
MIPI_CSI_RX_D0N: J10.11 M1.113(MIPI_CSI_RX_D0N)
MIPI_CSI_RX_D0P: J10.12 M1.114(MIPI_CSI_RX_D0P)
MIPI_CSI_RX_D1N: J10.14 M1.111(MIPI_CSI_RX_D1N)
MIPI_CSI_RX_D1P: J10.15 M1.112(MIPI_CSI_RX_D1P)
MIPI_CSI_RX_D2N: J10.20 M1.109(MIPI_CSI_RX_D2N)
MIPI_CSI_RX_D2P: J10.21 M1.110(MIPI_CSI_RX_D2P)
MIPI_CSI_RX_D3N: J10.23 M1.107(MIPI_CSI_RX_D3N)
MIPI_CSI_RX_D3P: J10.24 M1.108(MIPI_CSI_RX_D3P)
MIPI_DSI_TX0_CLKN/LVDS_TX0_CLKN: J7.17 M1.125(MIPI_DSI_TX0_CLKN/LVDS_TX0_CLKN)
MIPI_DSI_TX0_CLKP/LVDS_TX0_CLKP: J7.18 M1.126(MIPI_DSI_TX0_CLKP/LVDS_TX0_CLKP)
MIPI_DSI_TX0_D0N/LVDS_TX0_D0N: J7.8 M1.133(MIPI_DSI_TX0_D0N/LVDS_TX0_D0N)
MIPI_DSI_TX0_D0P/LVDS_TX0_D0P: J7.9 M1.134(MIPI_DSI_TX0_D0P/LVDS_TX0_D0P)
MIPI_DSI_TX0_D1N/LVDS_TX0_D1N: J7.11 M1.131(MIPI_DSI_TX0_D1N/LVDS_TX0_D1N)
MIPI_DSI_TX0_D1P/LVDS_TX0_D1P: J7.12 M1.132(MIPI_DSI_TX0_D1P/LVDS_TX0_D1P)
MIPI_DSI_TX0_D2N/LVDS_TX0_D2N: J7.14 M1.129(MIPI_DSI_TX0_D2N/LVDS_TX0_D2N)
MIPI_DSI_TX0_D2P/LVDS_TX0_D2P: J7.15 M1.130(MIPI_DSI_TX0_D2P/LVDS_TX0_D2P)
MIPI_DSI_TX0_D3N/LVDS_TX0_D3N: J7.20 M1.127(MIPI_DSI_TX0_D3N/LVDS_TX0_D3N)
MIPI_DSI_TX0_D3P/LVDS_TX0_D3P: J7.21 M1.128(MIPI_DSI_TX0_D3P/LVDS_TX0_D3P)
MIPI_DSI_TX1_CLKN: J8.27 M1.115(MIPI_DSI_TX1_CLKN)
MIPI_DSI_TX1_CLKP: J8.26 M1.116(MIPI_DSI_TX1_CLKP)
MIPI_DSI_TX1_D0N: J8.33 M1.123(MIPI_DSI_TX1_D0N)
MIPI_DSI_TX1_D0P: J8.32 M1.124(MIPI_DSI_TX1_D0P)
MIPI_DSI_TX1_D1N: J8.30 M1.121(MIPI_DSI_TX1_D1N)
MIPI_DSI_TX1_D1P: J8.29 M1.122(MIPI_DSI_TX1_D1P)
MIPI_DSI_TX1_D2N: J8.24 M1.119(MIPI_DSI_TX1_D2N)
MIPI_DSI_TX1_D2P: J8.23 M1.120(MIPI_DSI_TX1_D2P)
MIPI_DSI_TX1_D3N: J8.21 M1.117(MIPI_DSI_TX1_D3N)
MIPI_DSI_TX1_D3P: J8.20 M1.118(MIPI_DSI_TX1_D3P)
MIPI_DSI_TX1_RST: J8.36 R342.2
PHY_INT: R1219.1 U11.11(RXD2/INTB)
PMIC_32KHZ_OUT_WIFI: M1.180(PMIC_32KOUT) R74.1
PMIC_EXT_EN: M1.167(PMIC_EXT_EN) R11.1
PMIC_PWRON: D82.1 D82.10 J46.2 M1.168(PMIC_PWRON)
PMIC_VDC: D86.C M1.169(VDC) R18.1 R20.2
PWM0_M0_EDP: J5.8 M1.162(PWM0_M0/CPUAVS/GPIO0_B7_D)
PWM4_LVDS: J7.35 M1.155(PWM4/VOP_PWM_M0/MCU_JTAG_TRSTN/)
